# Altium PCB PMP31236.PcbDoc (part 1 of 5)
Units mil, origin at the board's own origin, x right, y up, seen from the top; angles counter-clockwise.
Board outline 6425 x 5322.16 mil, 6 copper layers (Top Layer, Power / GND 1, Signal Layer 1, Signal Layer 2, Power / GND 2, Bottom Layer), stack 78.712 mil thick; 732 components, 346 nets, 1735 pads, 719 vias.
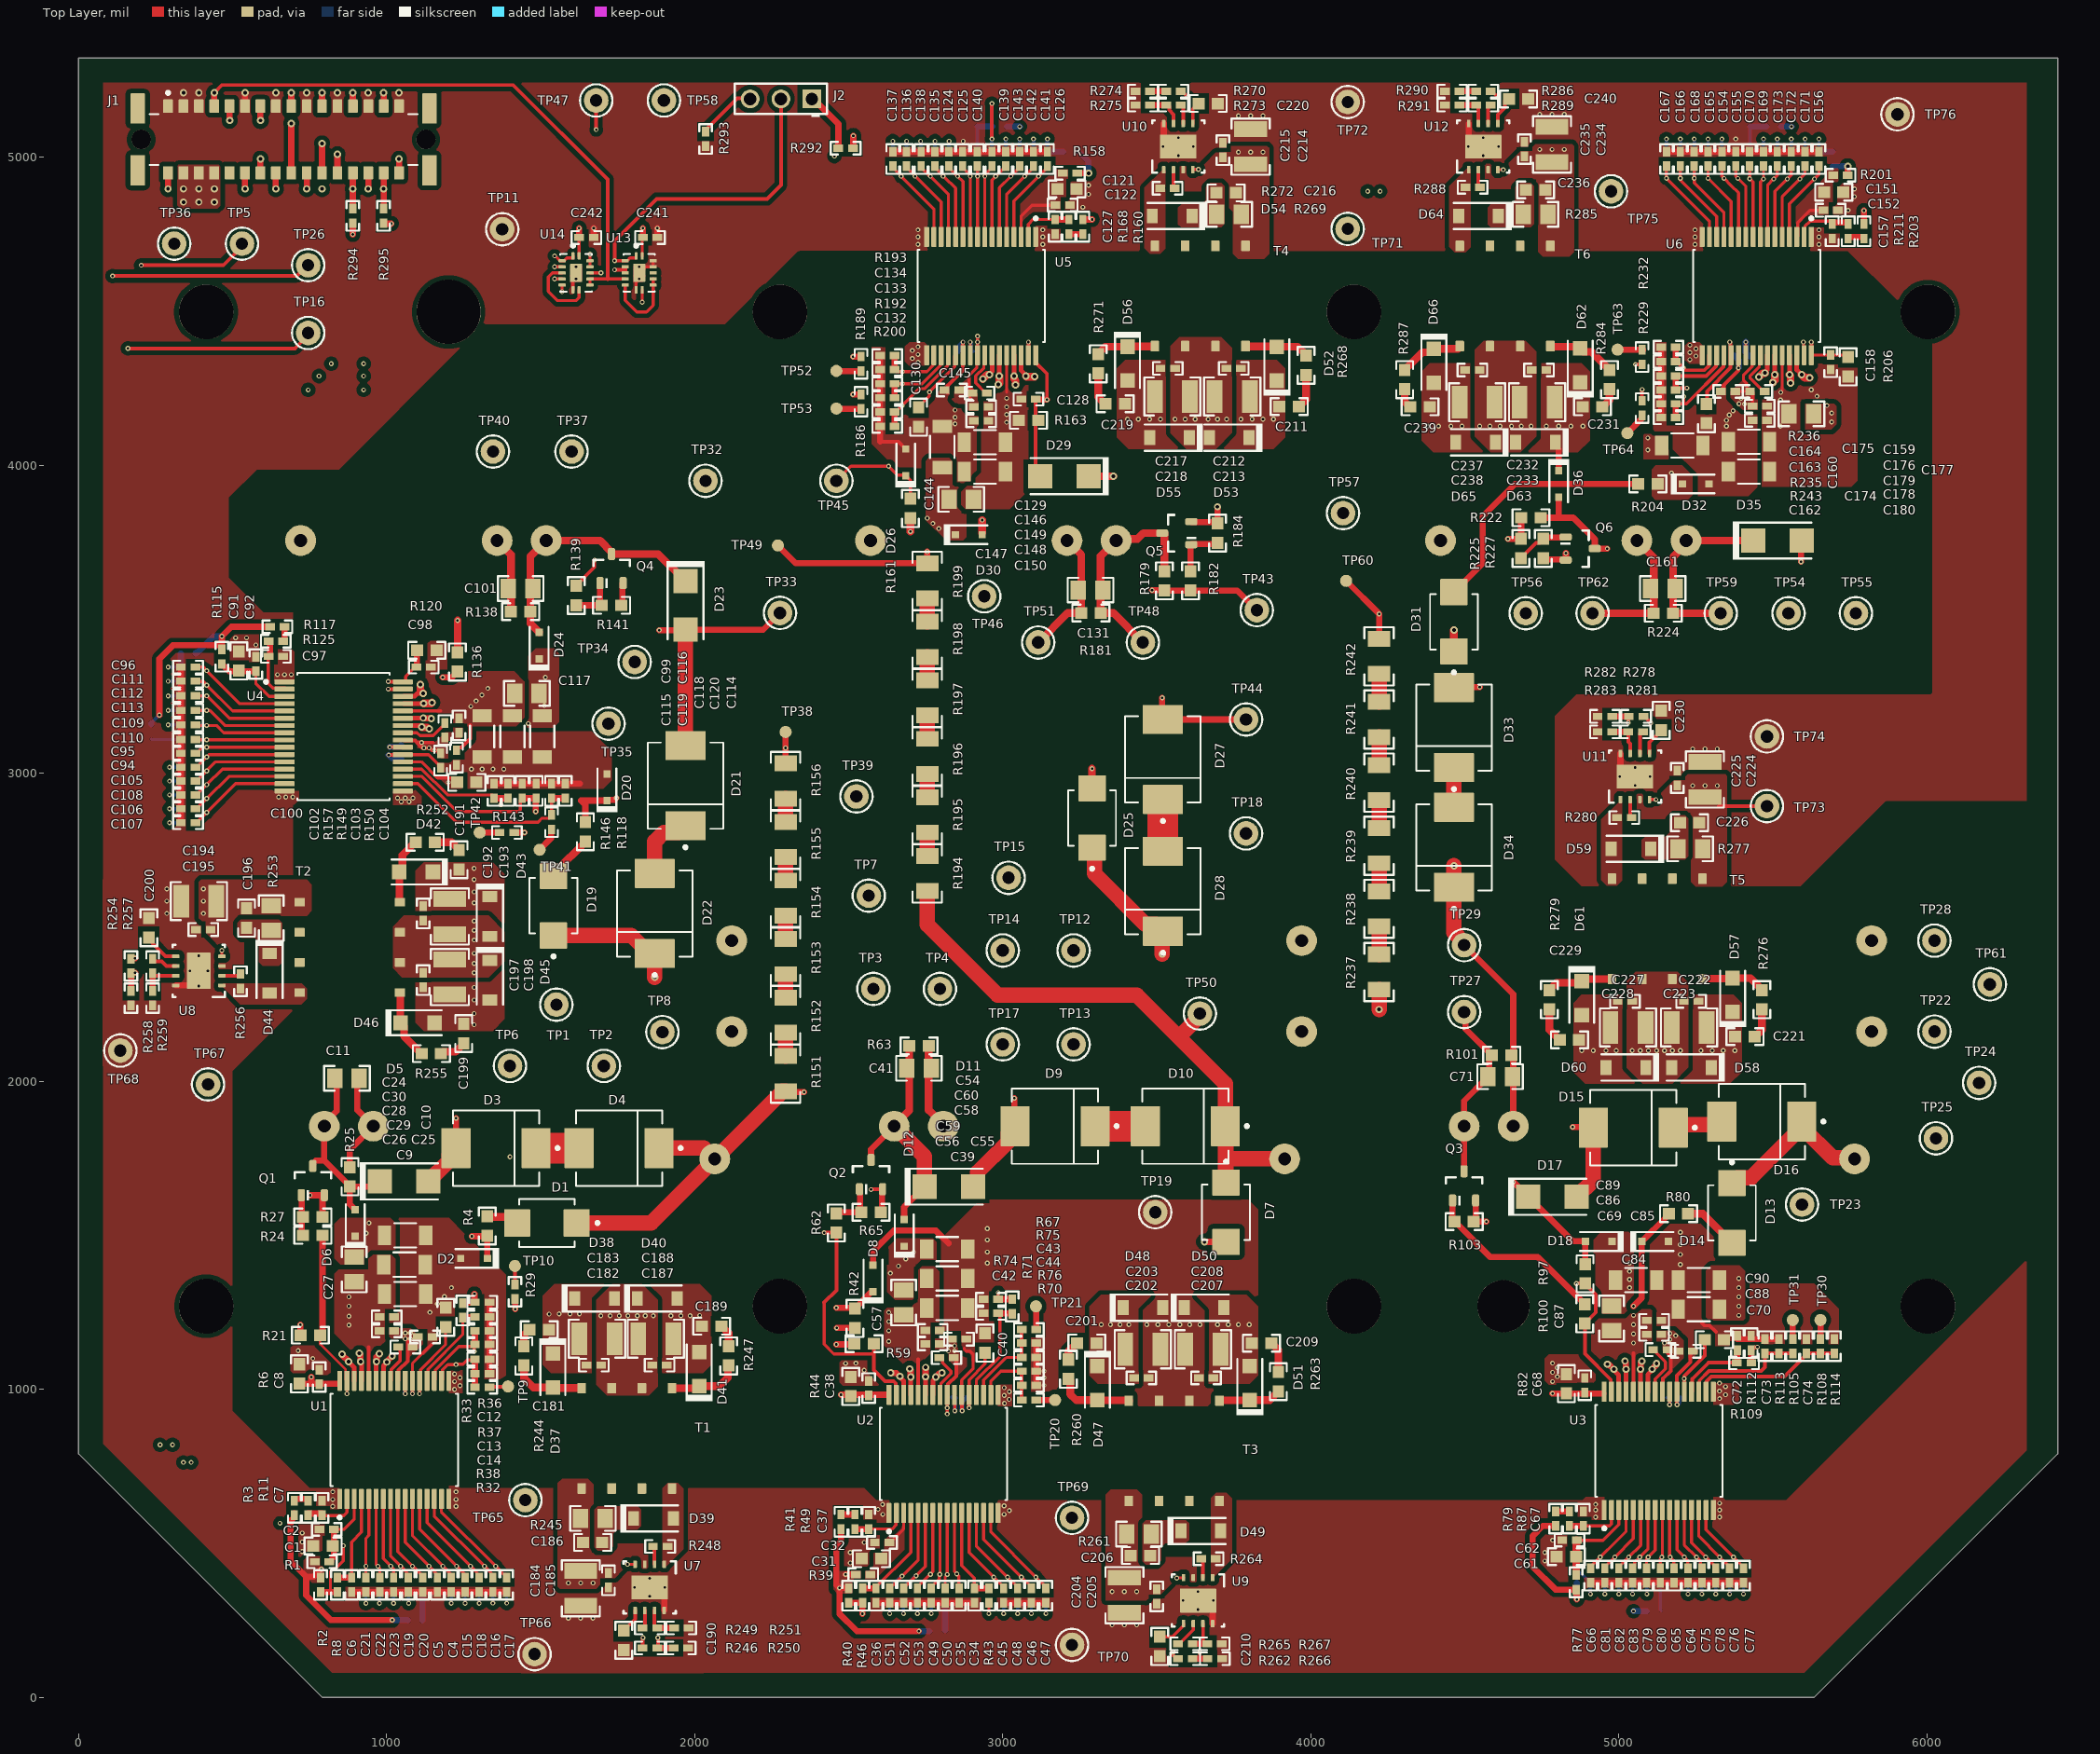
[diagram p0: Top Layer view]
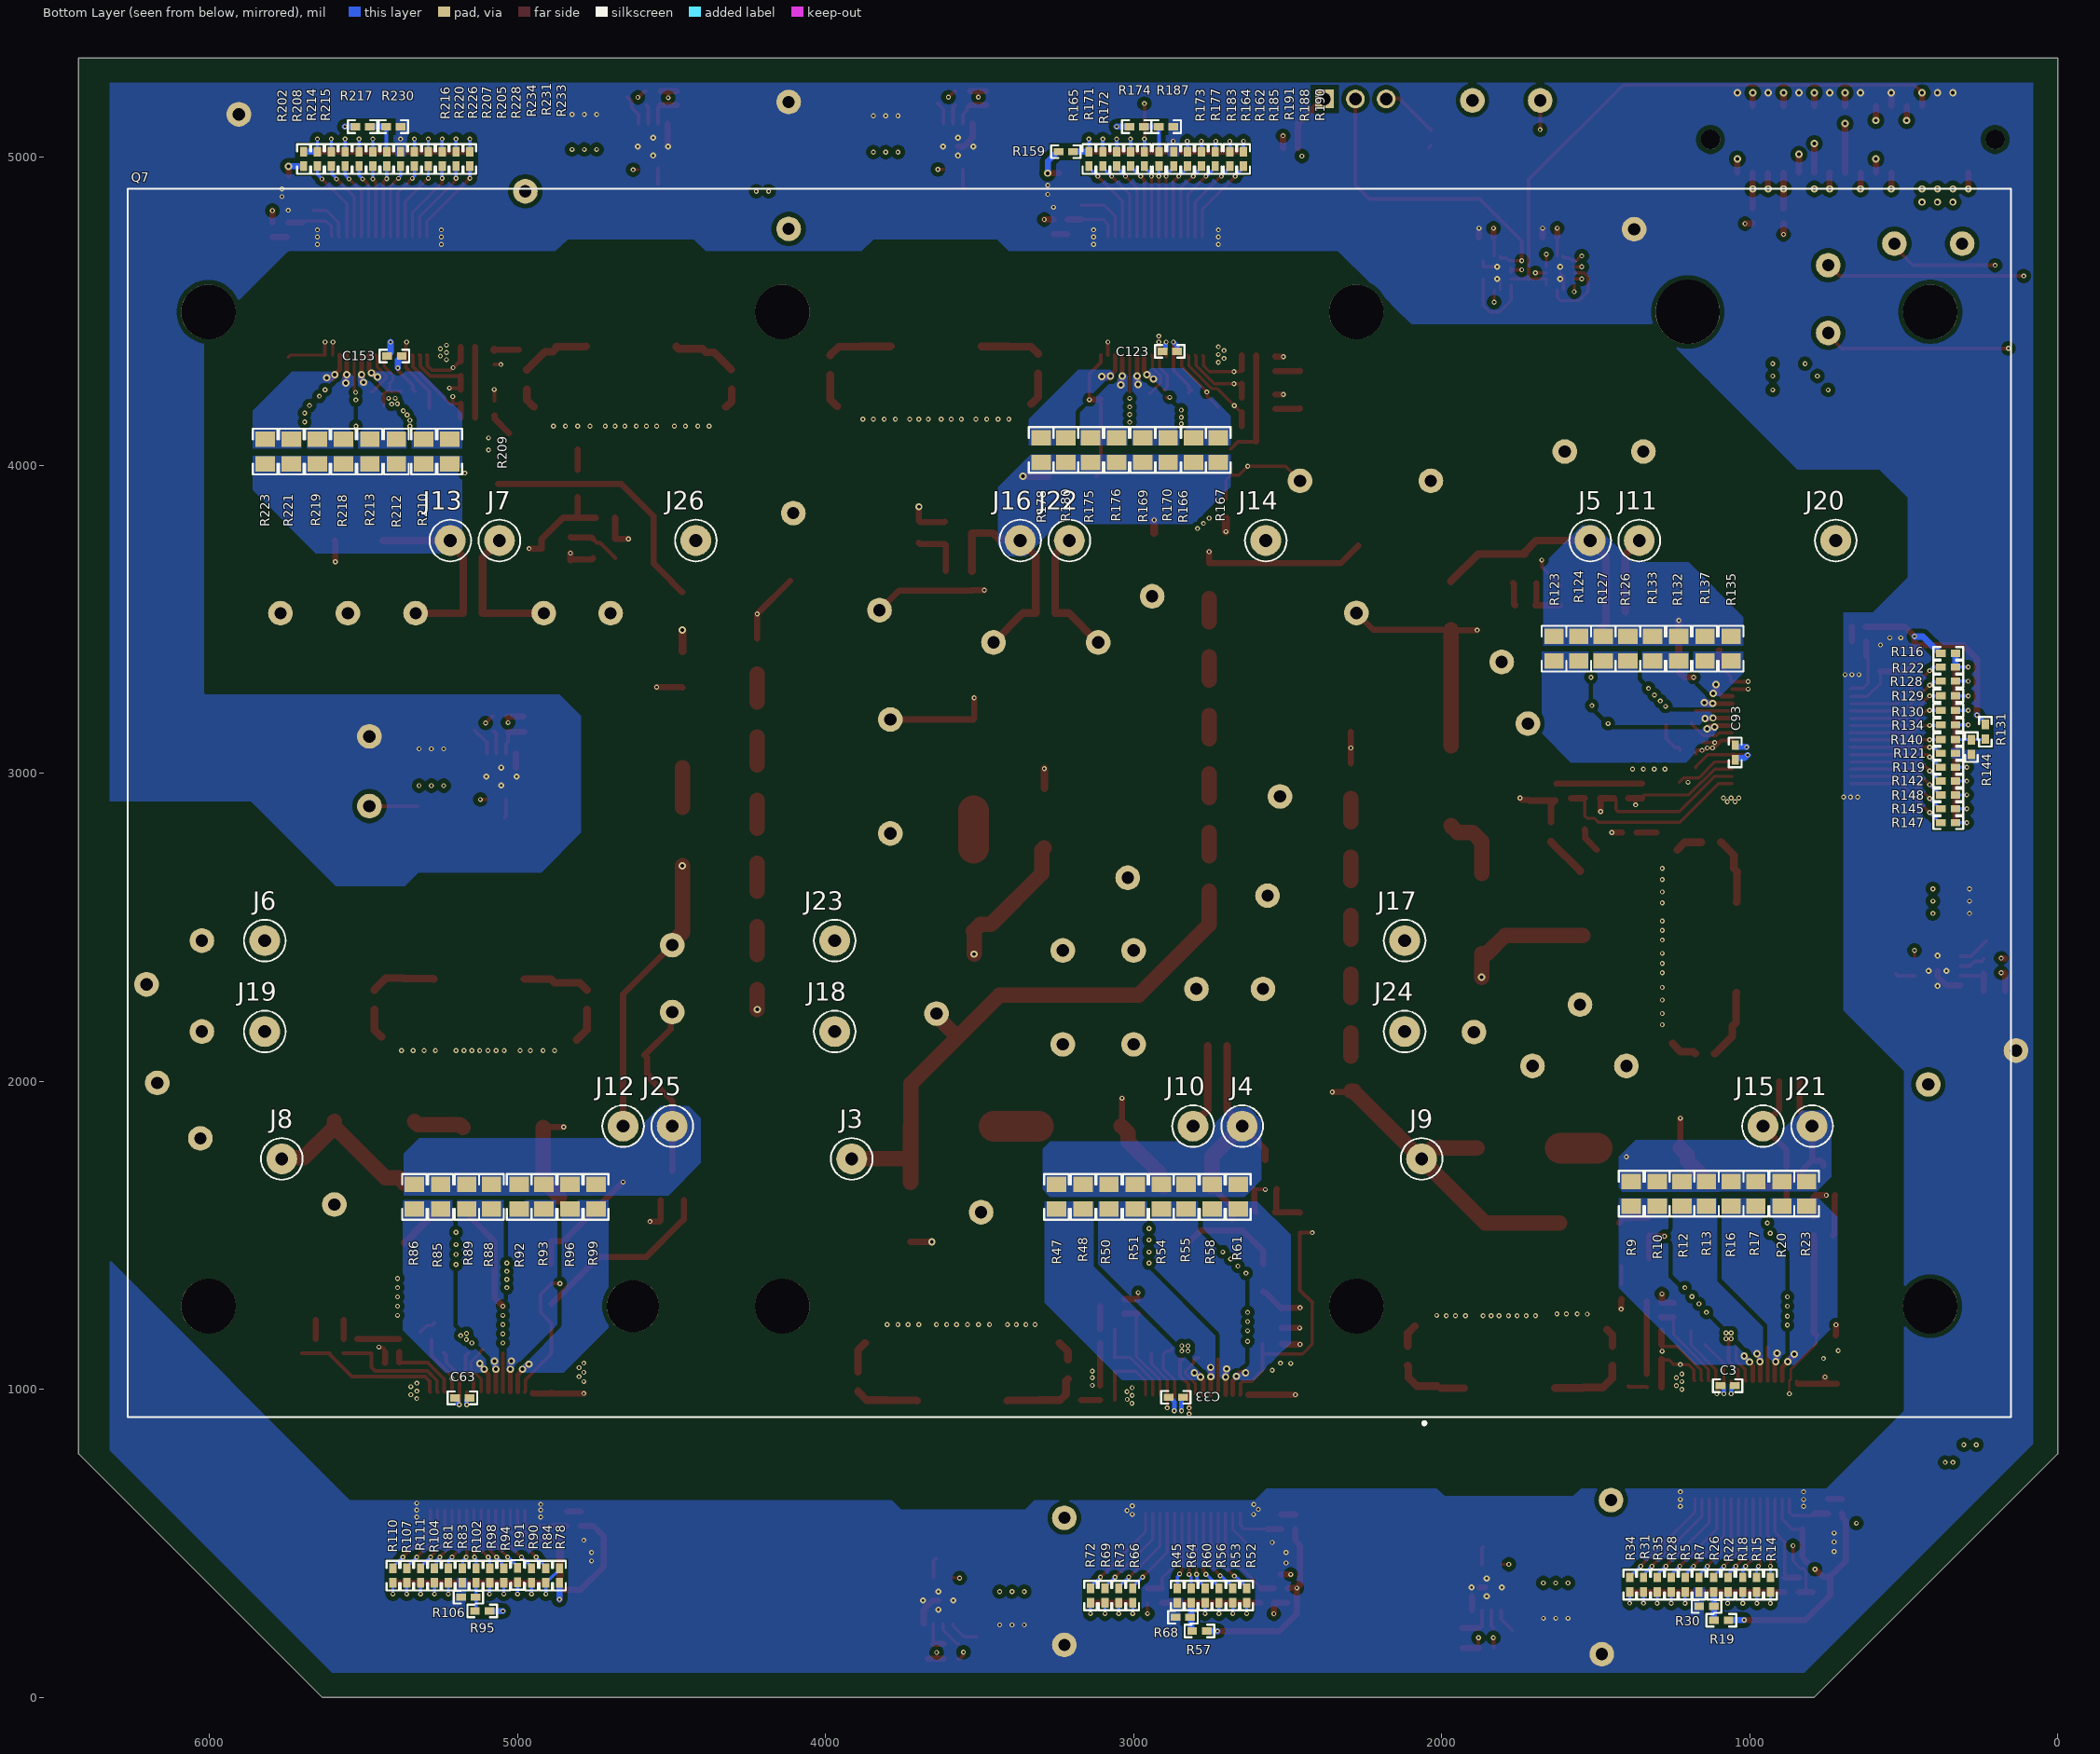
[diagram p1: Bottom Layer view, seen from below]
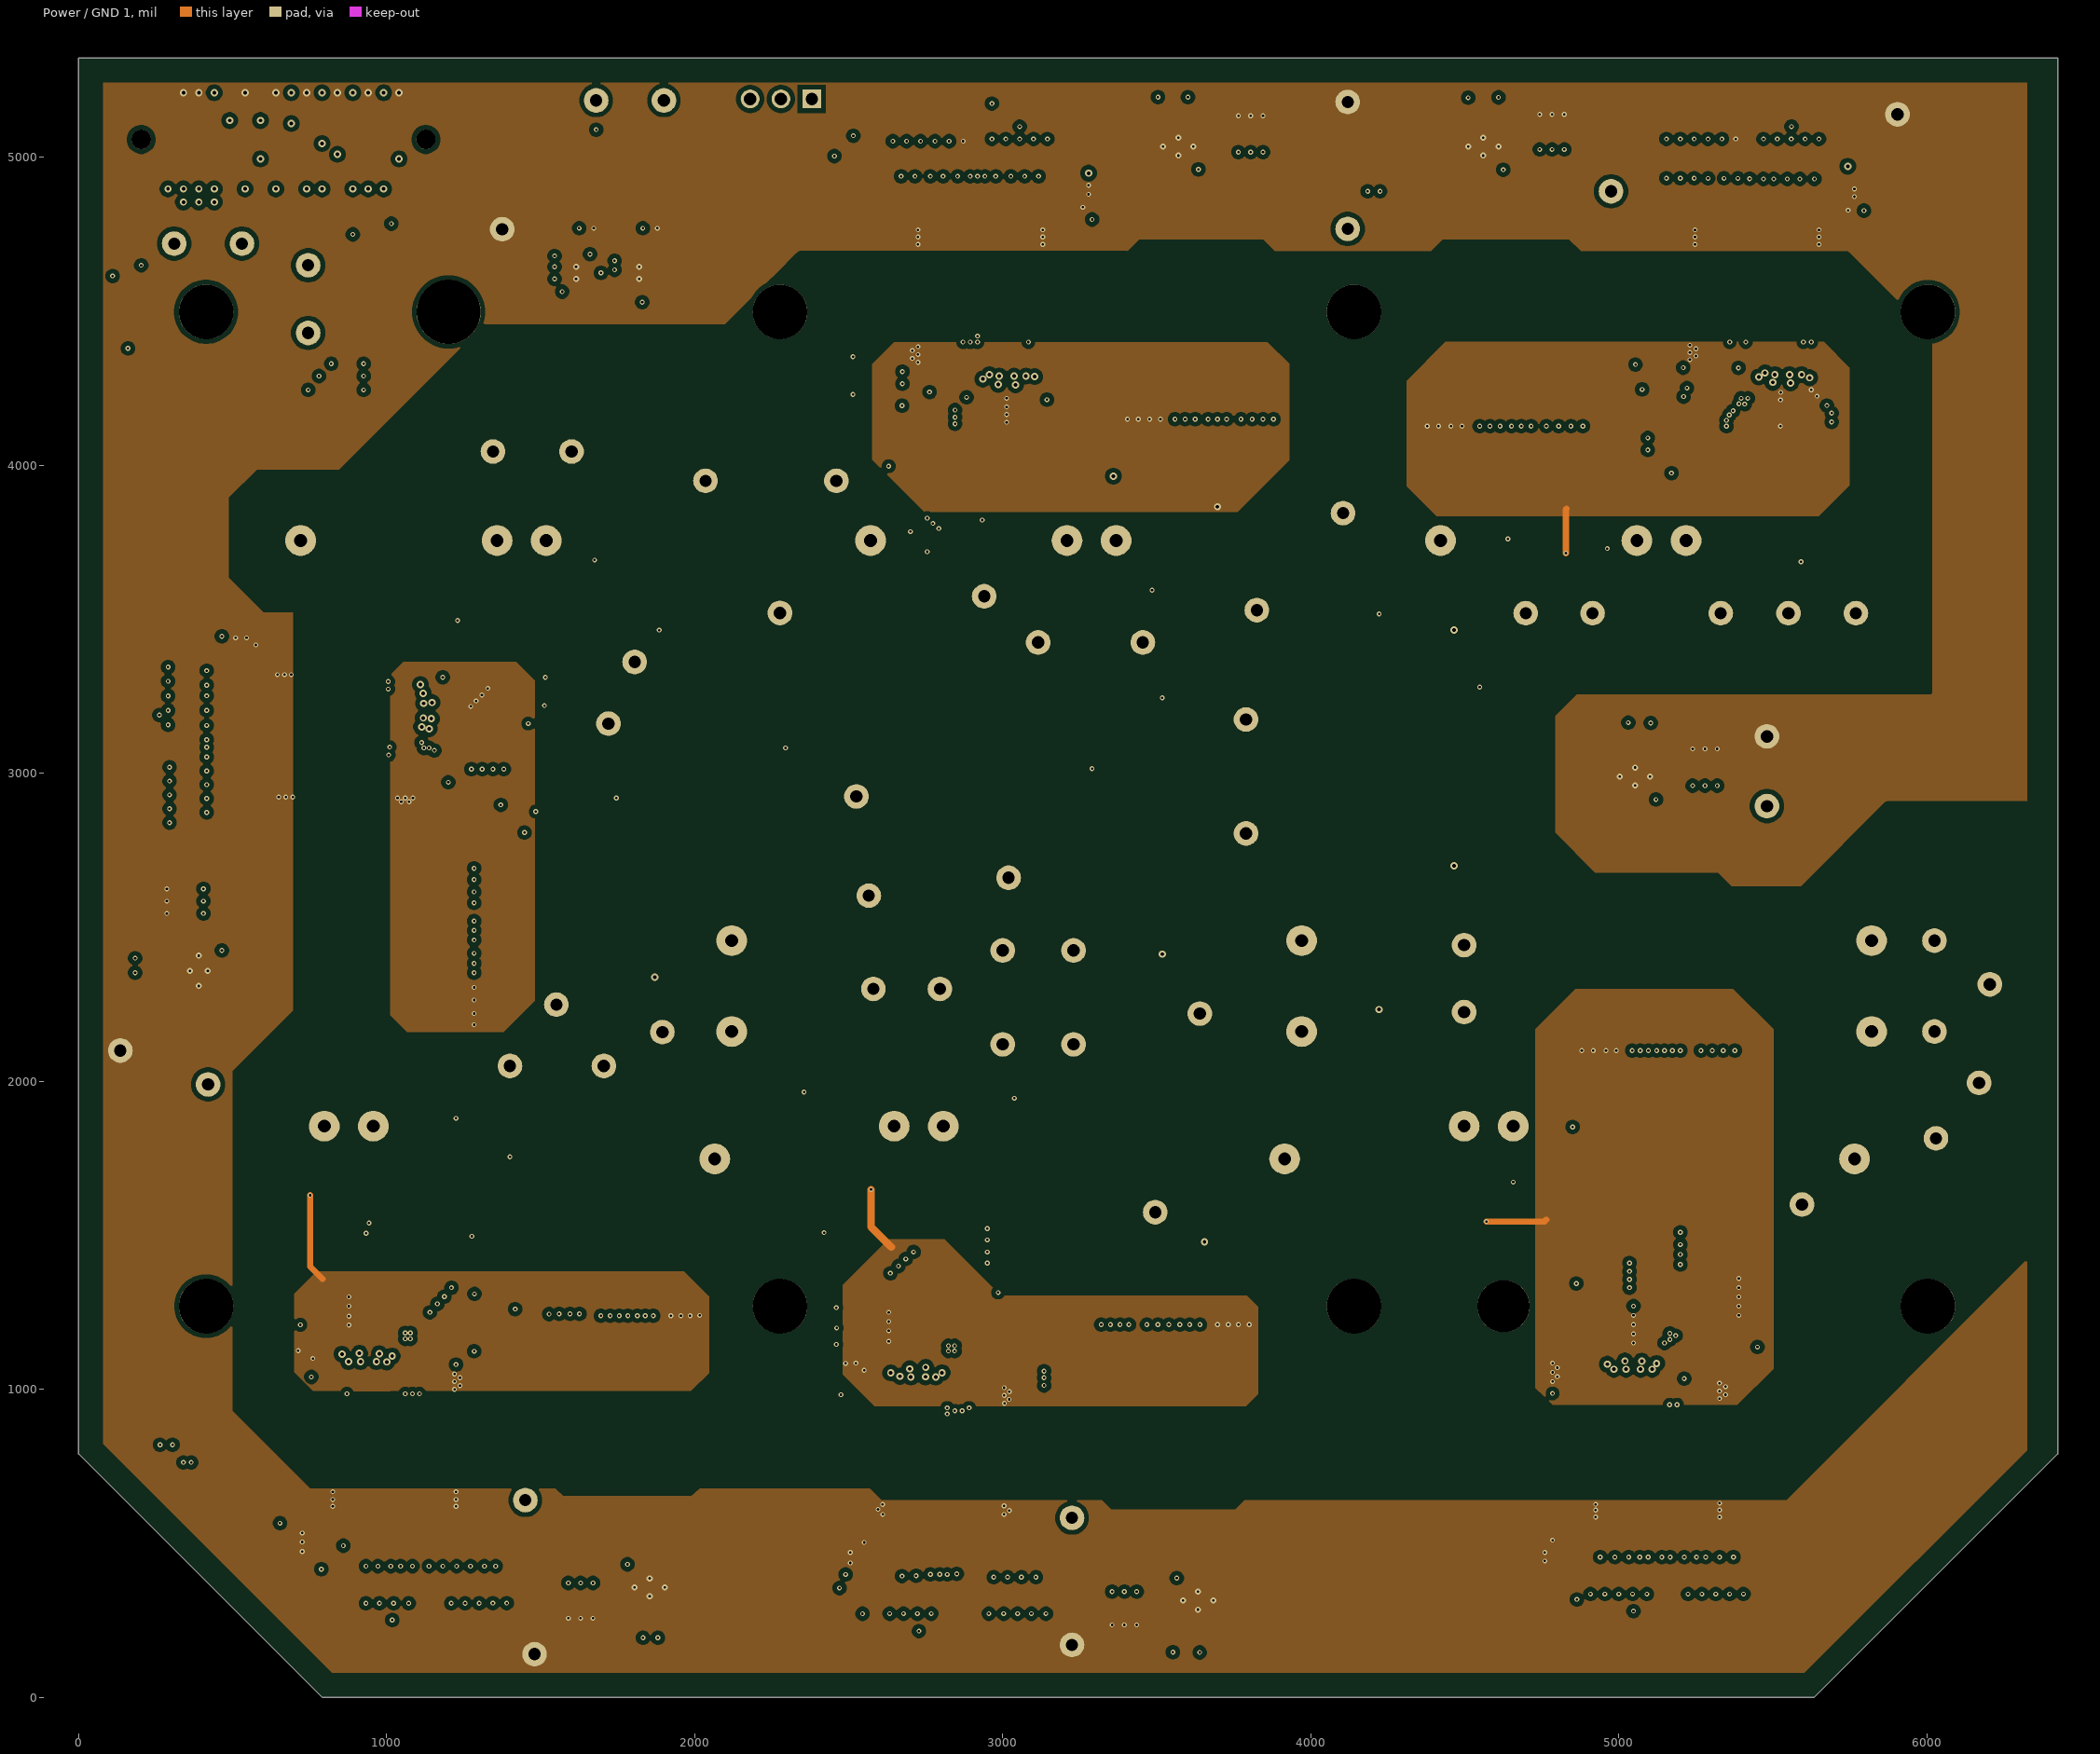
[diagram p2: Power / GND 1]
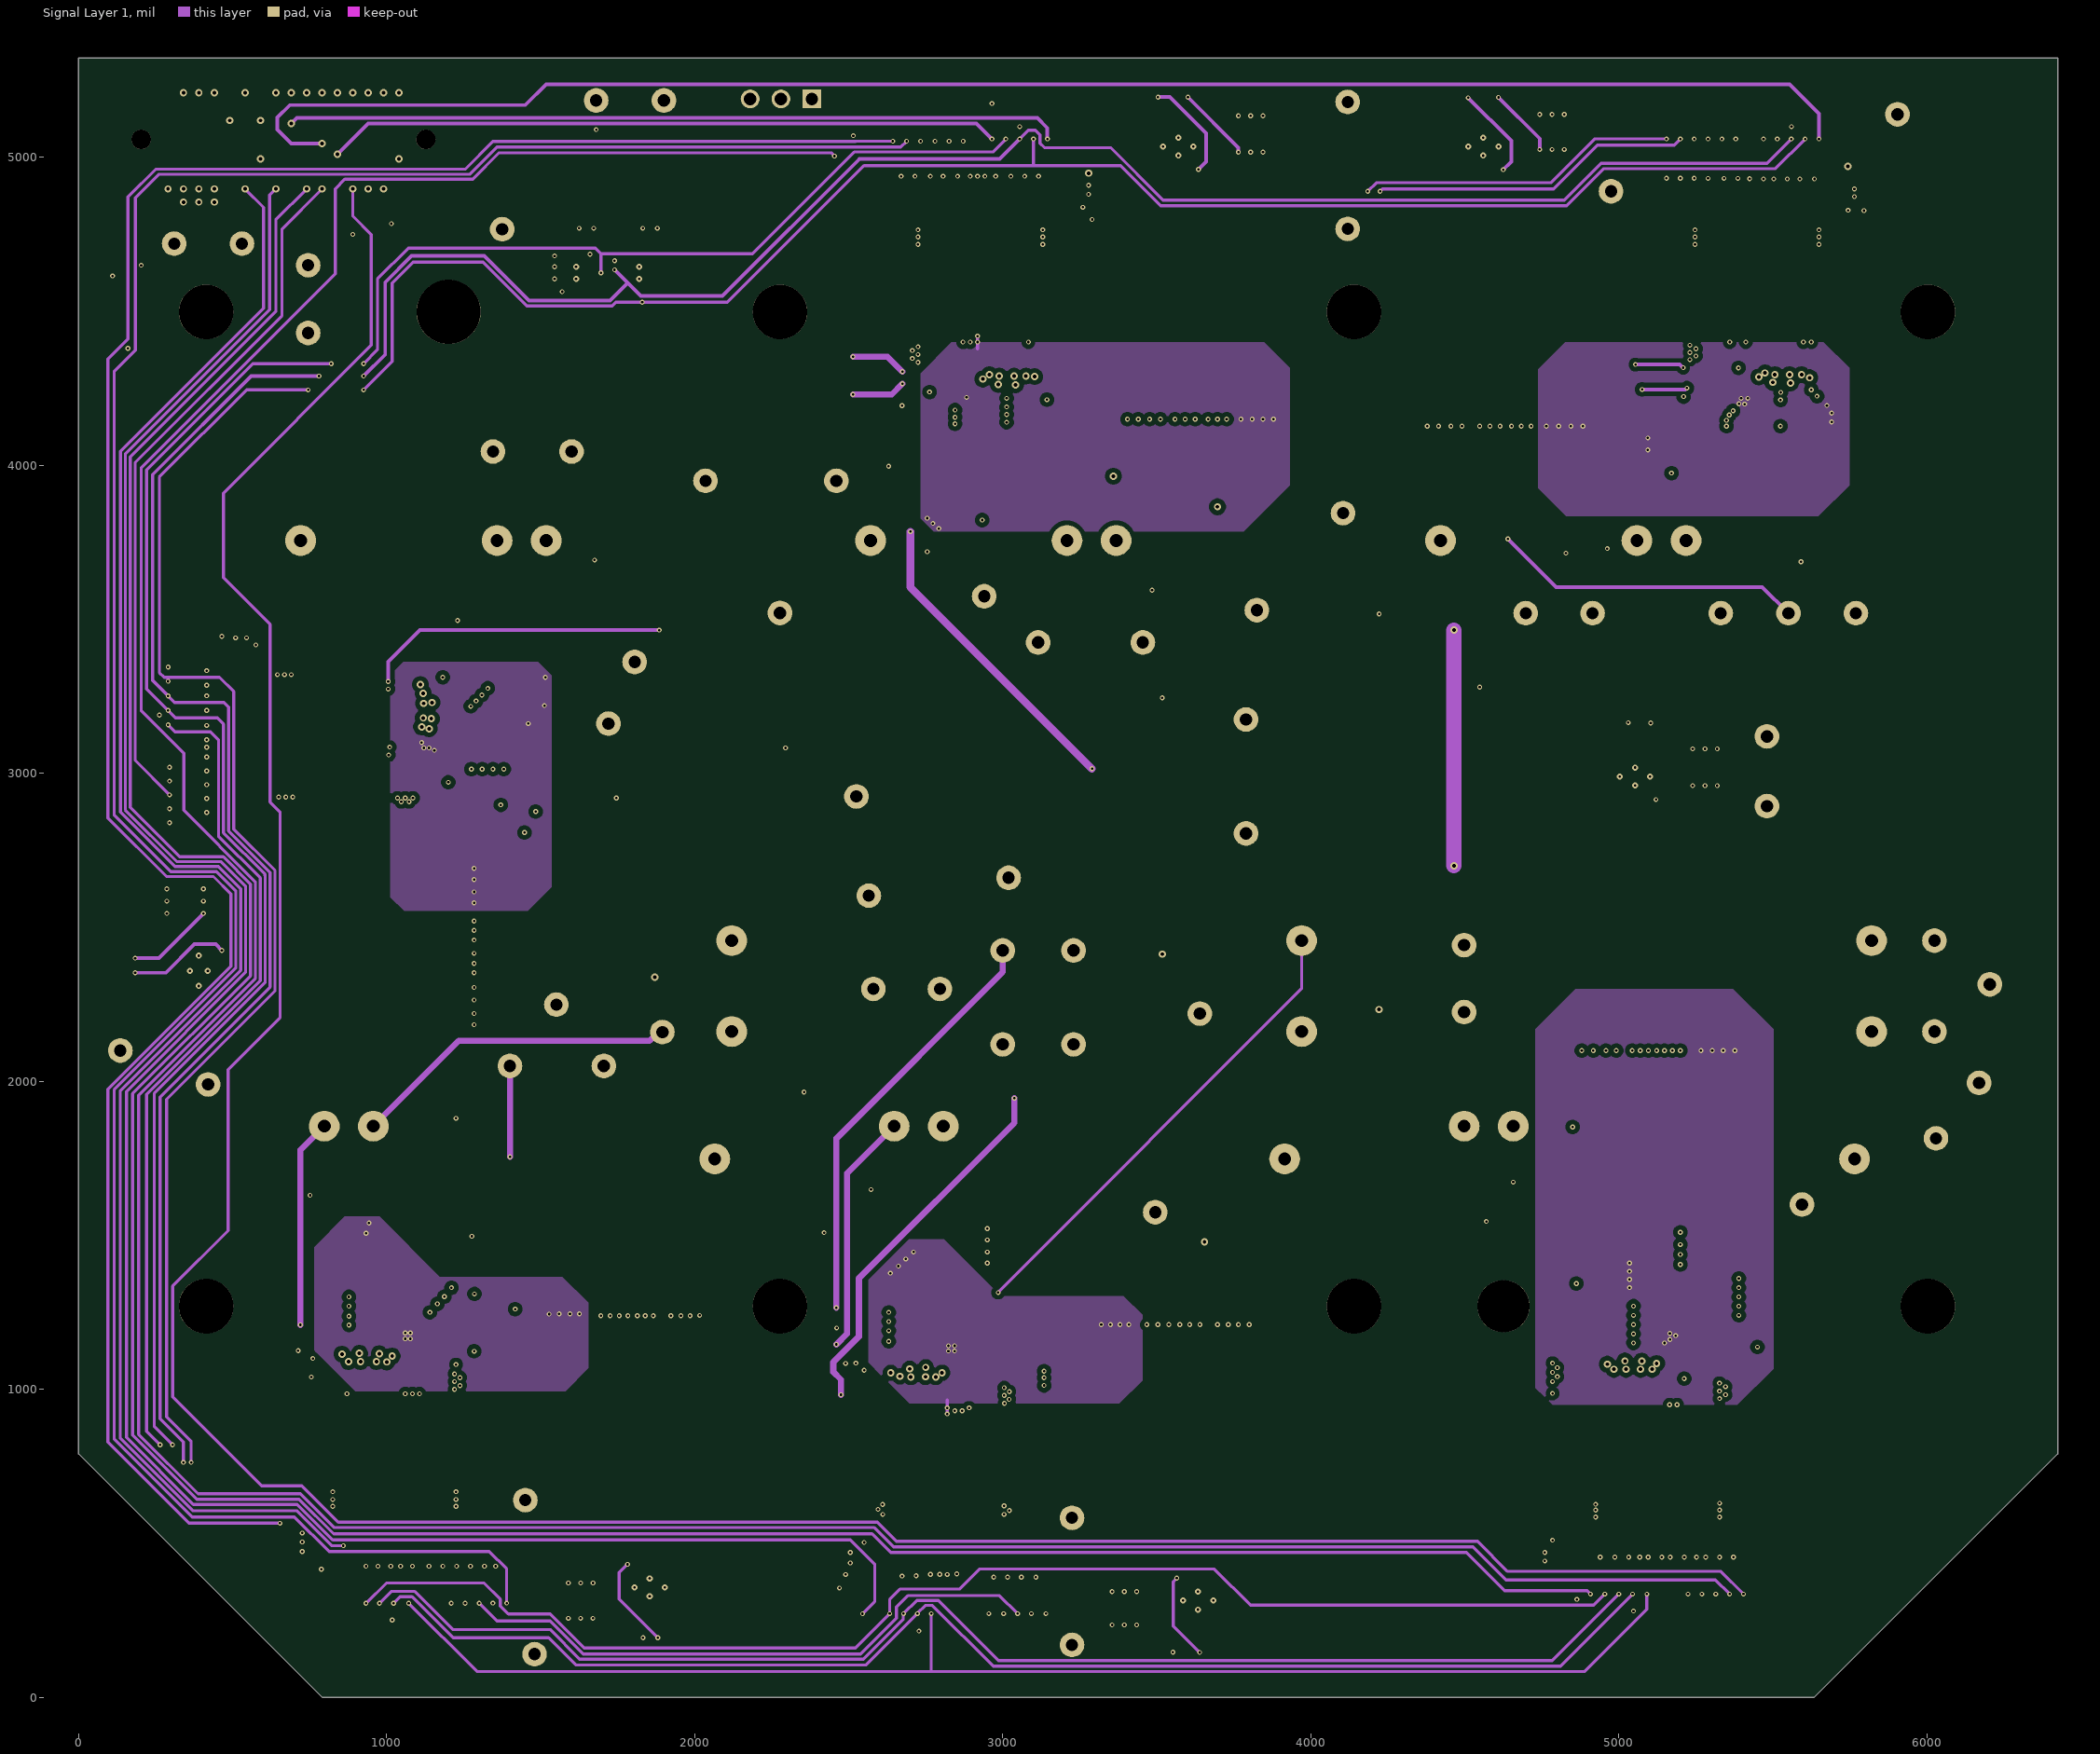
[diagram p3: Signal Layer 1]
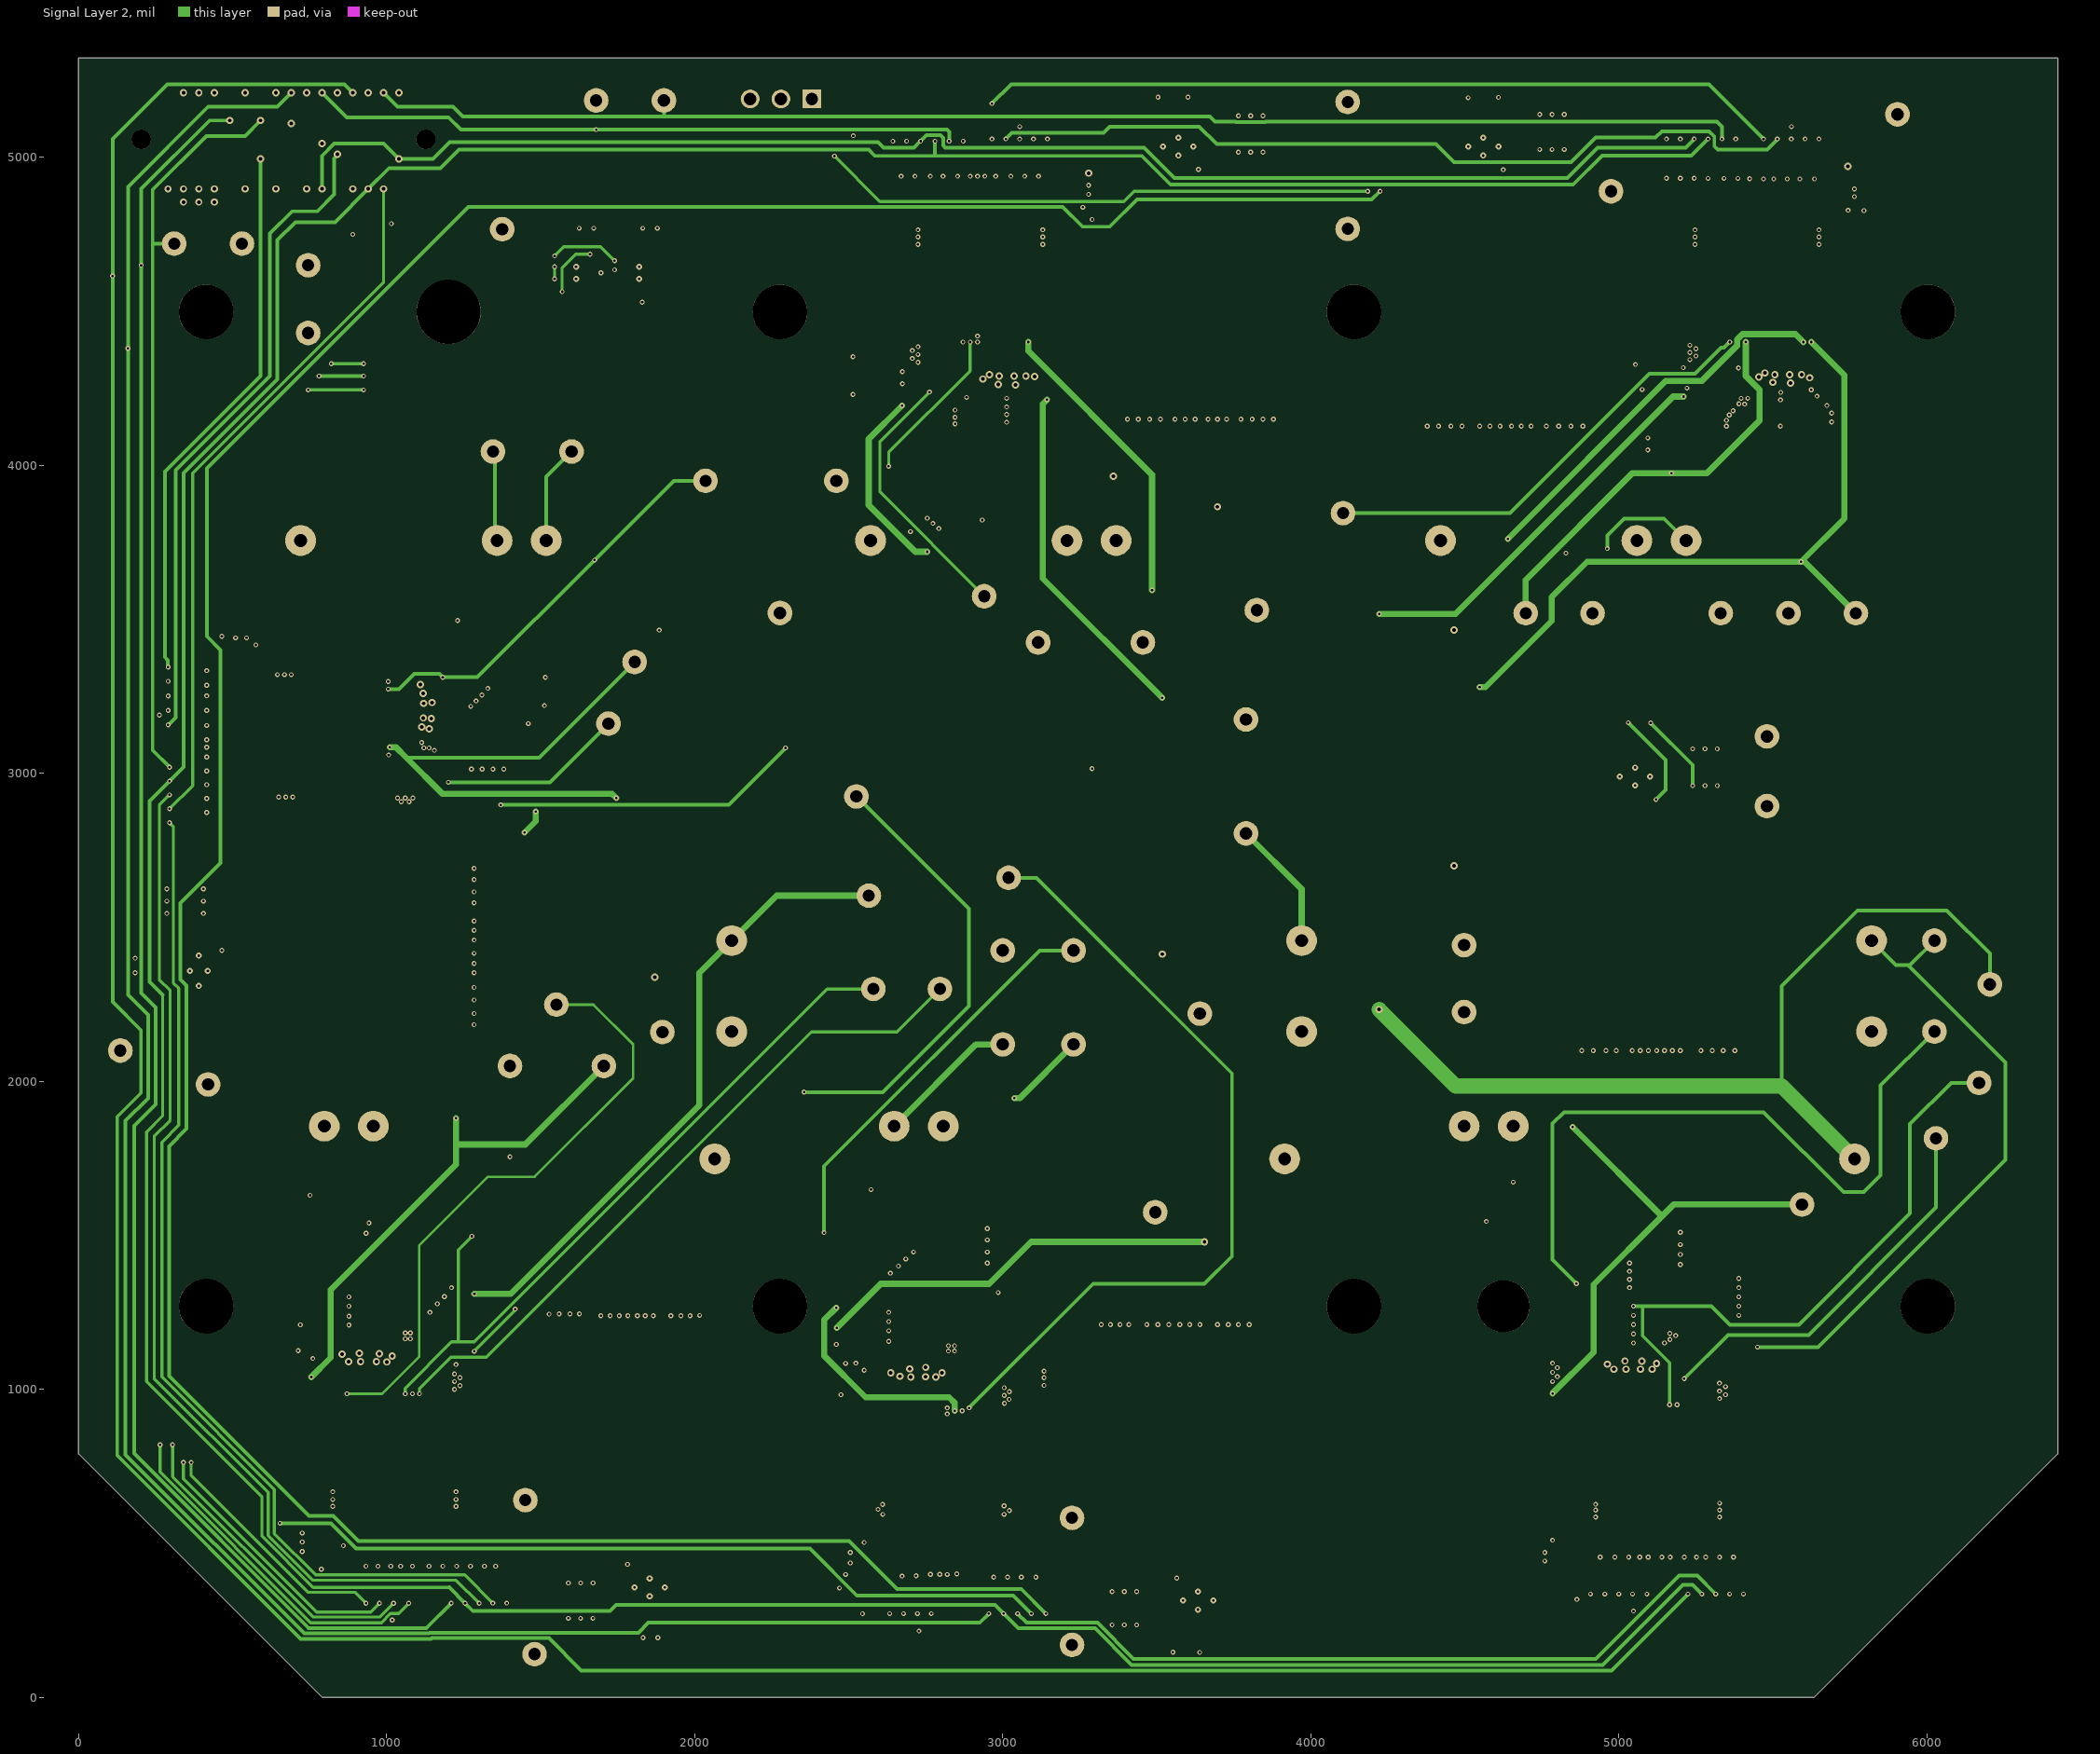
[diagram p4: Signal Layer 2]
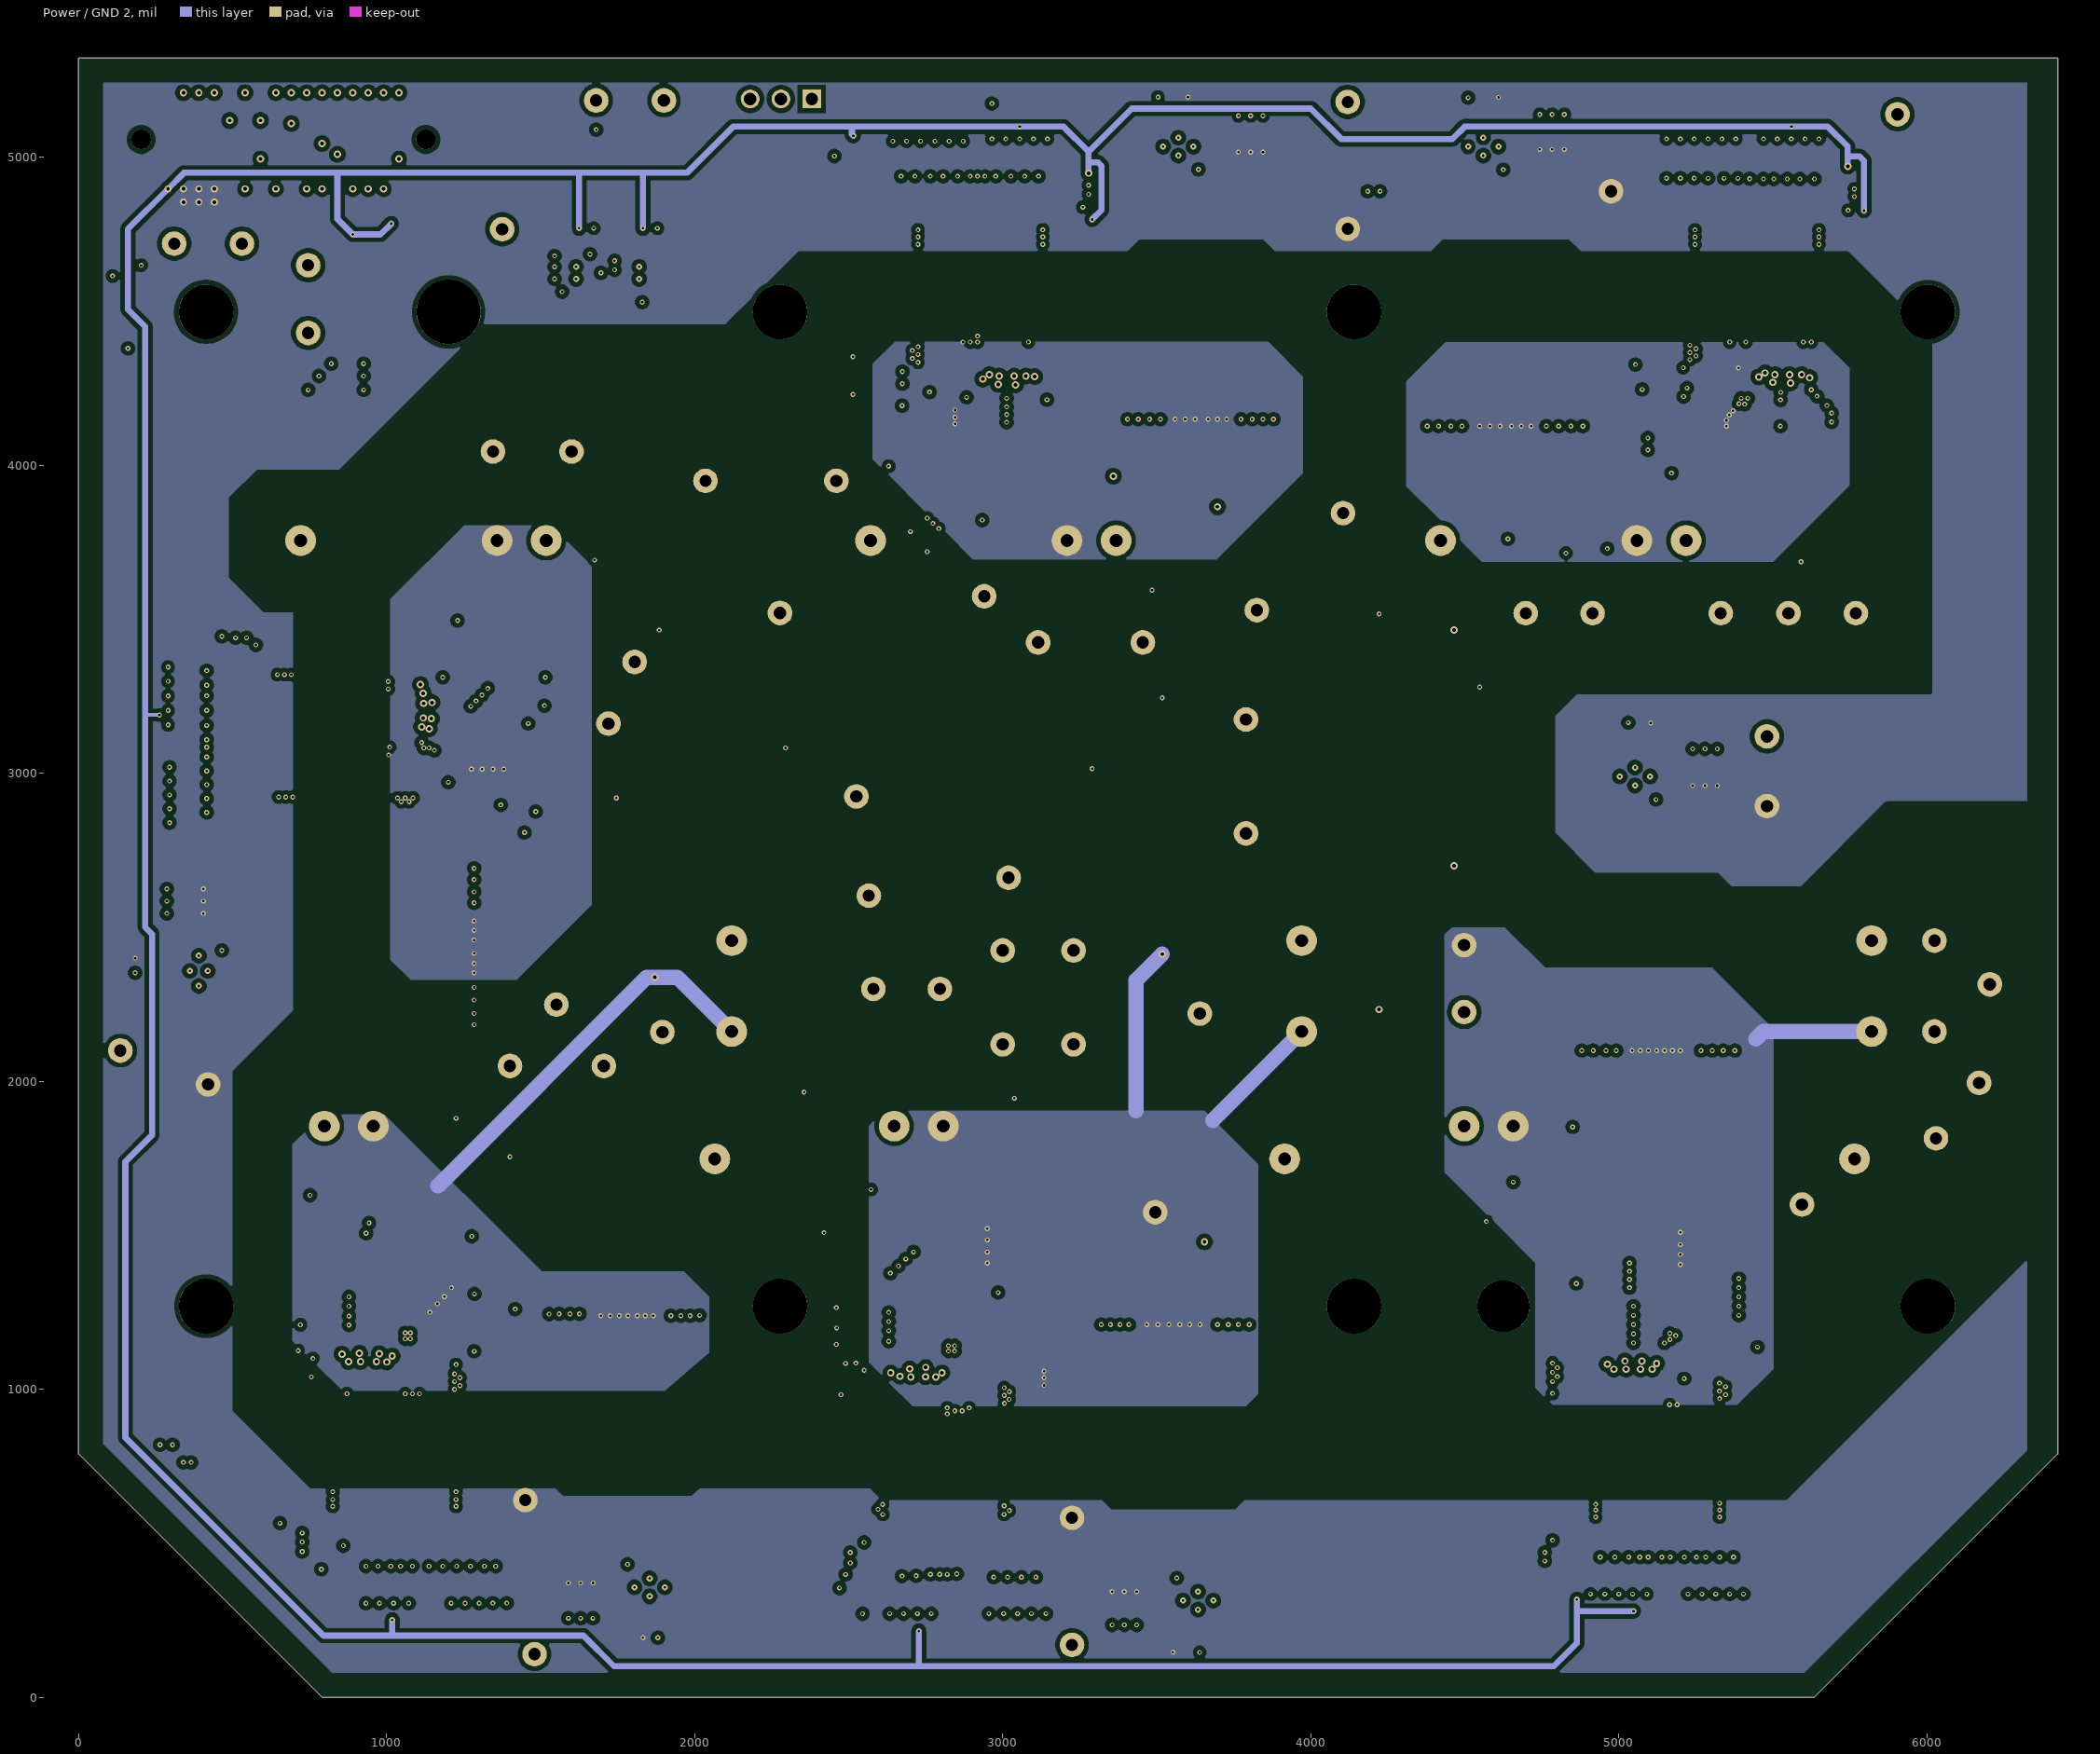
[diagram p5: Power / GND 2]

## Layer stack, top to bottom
Top Solder: solder mask 0.4, Solder Resist, Dk 3.5
Top Layer: signal copper 1.4
Dielectric 1: prepreg 2.8, PP-006, Dk 4.1
Power / GND 1: signal copper 1.378
Dielectric 3: prepreg 2.8, PP-006, Dk 4.1
Signal Layer 1: signal copper 1.378
Dielectric1: core 59.2, FR-4, Dk 4.8
Signal Layer 2: signal copper 1.378
Dielectric 4: prepreg 2.8, PP-006, Dk 4.1
Power / GND 2: signal copper 1.378
Dielectric 2: prepreg 2.8, PP-006, Dk 4.1
Bottom Layer: signal copper 1.4
Bottom Solder: solder mask 0.4, Solder Resist, Dk 3.5

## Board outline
5635,0 6425,790 6425,5322.16 0,5322.16 0,790 790,0

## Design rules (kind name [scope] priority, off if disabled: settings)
AcuteAngle [All] p1: minimum=4.50000000000000E+0001 checktracksonly=FALSE
AssemblyTestPointUsage [All] p1: valid=2
BoardOutlineClearance [All] p1: gap=78.74 ignorepadtopadclearanceinfootprint=FALSE
Clearance Clearance_Keepouts [((IsTrack Or IsArc) And Not InPoly) And IsFree and IsKeepOut vs ((IsTrack Or IsArc) And Not InPoly) And IsFree and IsKeepOut] p1: gap=0 ignorepadtopadclearanceinfootprint=FALSE
Clearance Clearance_BoardEdge_MountingHoles [OnCopper and InComponentClass('Mounting Holes') vs IsKeepOut] p2: gap=40 ignorepadtopadclearanceinfootprint=FALSE except(0: Arc-Hole Track-Hole SMDPad-Hole THPad-Hole Via-Hole Fill-Hole Poly-Hole Region-Hole Text-Hole)
Clearance Clearance_BoardEdge_Poly [OnCopper and InPoly vs IsKeepOut] p3: gap=25 ignorepadtopadclearanceinfootprint=FALSE except(0: Arc-Hole Track-Hole SMDPad-Hole THPad-Hole Via-Hole Fill-Hole Poly-Hole Region-Hole Text-Hole)
Clearance Clearance_BoardEdge [OnCopper and Not InComponentClass('Logo') and not InComponentClass('FiducialMark') and not InRegion(1000,500,4000,800) and Not IsKeepout vs IsKeepOut] p4: gap=75 ignorepadtopadclearanceinfootprint=FALSE except(0: Arc-Hole Track-Hole SMDPad-Hole THPad-Hole Via-Hole Fill-Hole Poly-Hole Region-Hole Text-Hole)
Clearance Clearance_Poly [InPolygon] p5: gap=15 ignorepadtopadclearanceinfootprint=FALSE except(0: Arc-Hole Track-Hole SMDPad-Hole THPad-Hole Via-Hole Fill-Hole Poly-Hole Region-Hole Text-Hole)
Clearance [All] p6: gap=5.91 ignorepadtopadclearanceinfootprint=FALSE
ComponentClearance ComponentClearance_MountingHoles_FiducialMarks [InComponentClass('Mounting Holes') vs InComponentClass('FiducialMark')] p1: gap=50 collisioncheckmode=3 verticalgap=10 showdistances=FALSE
ComponentClearance ComponentClearance_Shunt [InComponentClass('Header') vs InComponentClass('Shunt')] p2: gap=0 collisioncheckmode=3 verticalgap=0 showdistances=FALSE
ComponentClearance ComponentClearance_Logo [InComponentClass('Logo')] p3: gap=50 collisioncheckmode=3 verticalgap=10 showdistances=FALSE
ComponentClearance ComponentClearance_ScrewToNut [(HasFootprint('NY PMS 440 0025 PH')) vs (HasFootprint('Keystone_1902C'))] p4: gap=5 collisioncheckmode=3 verticalgap=10 showdistances=FALSE
ComponentClearance ComponentClearance_MountingHoles [InComponentClass('Mounting Holes')] p5: gap=250 collisioncheckmode=3 verticalgap=100000 showdistances=FALSE
ComponentClearance ComponentClearance_SmallPassives [HasFootprint('0201*') or HasFootprint('0402*') or HasFootprint('0508') or HasFootprint('0603*') or HasFootprint('0612') or HasFootprint('0805*') or HasFootprint('0815*') or HasFootprint('0830*') or HasFootprint('1206*') or HasFootprint('1210*') or HasFootprint('1808*') or HasFootprint('1812*') or HasFootprint('1825*') or HasFootprint('2010*') or HasFootprint('2220*') or HasFootprint('2225*') or HasFootprint('2512*') or HasFootprint('2728*') or HasFootprint('3518*') vs HasFootprint('0201*') or HasFootprint('0402*') or HasFootprint('0508') or HasFootprint('0603*') or HasFootprint('0612') or HasFootprint('0805*') or HasFootprint('0815*') or HasFootprint('0830*') or HasFootprint('1206*') or HasFootprint('1210*') or HasFootprint('1808*') or HasFootprint('1812*') or HasFootprint('1825*') or HasFootprint('2010*') or HasFootprint('2220*') or HasFootprint('2225*') or HasFootprint('2512*') or HasFootprint('2728*') or HasFootprint('3518*')] p6: gap=20 collisioncheckmode=3 verticalgap=10 showdistances=FALSE
ComponentClearance ComponentClearance_THtoSMT [IsThruComponent vs IsSMTComponent] p7: gap=100 collisioncheckmode=3 verticalgap=30 showdistances=FALSE
ComponentClearance ComponentClearance_THtoTH [IsThruComponent vs IsThruComponent] p8: gap=118.11 collisioncheckmode=3 verticalgap=30 showdistances=FALSE
ComponentClearance [All] p9: gap=40 collisioncheckmode=3 verticalgap=10 showdistances=FALSE
DiffPairsRouting [All] p1: maxlimit=100 minlimit=10 mostfreqgap=10 toplayer_minwidth=15 toplayer_maxwidth=15 toplayer_prefwidth=15 midlayer1_minwidth=15 midlayer1_maxwidth=15 midlayer1_prefwidth=15 midlayer2_minwidth=15 midlayer2_maxwidth=15 midlayer2_prefwidth=15 midlayer3_minwidth=15 midlayer3_maxwidth=15 midlayer3_prefwidth=15 midlayer4_minwidth=15 midlayer4_maxwidth=15 midlayer4_prefwidth=15 bottomlayer_minwidth=15 bottomlayer_maxwidth=15 bottomlayer_prefwidth=15 maxuncoupledlength=1000
FabricationTestPointUsage TestPointUsage [All] p1: valid=2 allowmultiple=FALSE
FabricationTestpoint Testpoint [All] p1: side=3 testpointundercomponent=TRUE minsize=40 maxsize=100 preferedsize=60 minholesize=0 maxholesize=40 preferedholesize=32 testpointgrid=1 allowsidetop=TRUE allowsidebottom=TRUE usegrid=TRUE gridtolerance=0.01
FanoutControl Fanout_LCC [IsLCC] p1: bgadir=Out bgaviamode=Centered fanoutstyle=Auto fanoutdirection=Alternating viagrid=1 // Fanout_LCC (Default Rule)
FanoutControl Fanout_BGA [IsBGA] p2: bgadir=Out bgaviamode=Centered fanoutstyle=Auto fanoutdirection=Alternating viagrid=1 // Fanout_BGA (Default Rule)
FanoutControl Fanout_Default [All] p4: bgadir=Out bgaviamode=Centered fanoutstyle=Auto fanoutdirection=Alternating viagrid=1 // Fanout_Default (Default Rule)
FanoutControl Fanout_Small [(CompPinCount < 5)] p5: bgadir=Out bgaviamode=Centered fanoutstyle=Auto fanoutdirection=OutThenIn viagrid=1 // Fanout_Small (Default Rule)
HoleSize [All] p1: absolutevalues=TRUE maxlimit=251 minlimit=7.87 maxpercent=80.000 minpercent=20.000
MinimumAnnularRing MinimumAnnularRing_ThermalPadVias [IsVia and InAnyComponent] p1: minimumring=5.91
MinimumAnnularRing [All] p2: minimumring=3.94
MinimumSolderMaskSliver MinimumSolderMaskSliver_Logo [InComponentClass('Logo') vs InComponentClass('Logo')] p1: minsoldermaskwidth=0.7
MinimumSolderMaskSliver [All] p2: minsoldermaskwidth=3.94
PlaneConnect [All] p1: planeconnectstyle=Relief reliefexpansion=10 reliefentries=4 reliefconductorwidth=10 reliefairgap=10
PolygonConnect [All] p1: connectstyle=Direct reliefconductorwidth=10 reliefentries=4 polygonreliefangle="90 Angle" airgapwidth=10
RoutingVias ThermalPadVias [IsVia and InAnyComponent] p1: holewidth=7.87 width=19.68 viastyle="Through Hole" minholewidth=7.87 minwidth=15.75 maxholewidth=12.99 maxwidth=23.62
RoutingVias [All] p2: holewidth=11.81 width=23.62 viastyle="Through Hole" minholewidth=7.87 minwidth=15.75 maxholewidth=40 maxwidth=65
SilkToBoardRegionClearance [Not ((IsComment or IsDesignator) And (Hide <> 'False')) and not InRegion(1000,500,4000,800)] p1:
SilkToSilkClearance SilkToSilkClearance_Pb-FreeLogo [(HasFootprint('Pb-Free_Overlay_Medium') OR HasFootprint('Pb-Free_Overlay_Small')) vs (HasFootprint('Pb-Free_Overlay_Medium') OR HasFootprint('Pb-Free_Overlay_Small'))] p1: silktosilkclearance=0
SilkToSilkClearance [All] p2: silktosilkclearance=4
SilkToSolderMaskClearance SilkToComonentPadClearance [IsPad and InAnycomponent] p1: minsilkscreentomaskgap=5 clearancetoexposedcopper=TRUE
SilkToSolderMaskClearance "Silk to Solder Mask Opening" [All] p2: minsilkscreentomaskgap=4 clearancetoexposedcopper=FALSE
SolderMaskExpansion [All] p1: expansion=1.97 istentingtop=FALSE
Width [All] p1: maxlimit=100 minlimit=6 preferedwidth=10 checkconnectedcopper=TRUE
15 further rules are at their usual default settings.

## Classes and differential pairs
component class PMP31236RevA_IGBT_Module: J3 J4 J5 J6 J7 J8 J9 J10 J11 J12 J13 J14 J15 J16 J17 J18 J19 J20 J21 J22 J23 J24 J25 J26 Q7
component class PMP31236RevA_Supply_W: C221 C222 C223 C224 C225 C226 C227 C228 C229 C230 C231 C232 C233 C234 C235 C236 C237 C238 C239 C240 D57 D58 D59 D60 D61 D62 D63 D64 D65 D66 R276 R277 R278 R279 R280 R281 R282 R283 R284 R285 R286 R287 R288 R289 R290 R291 T5 T6 TP73 TP74 TP75 TP76 U11 U12
component class PMP31236RevA_Supply_V: C201 C202 C203 C204 C205 C206 C207 C208 C209 C210 C211 C212 C213 C214 C215 C216 C217 C218 C219 C220 D47 D48 D49 D50 D51 D52 D53 D54 D55 D56 R260 R261 R262 R263 R264 R265 R266 R267 R268 R269 R270 R271 R272 R273 R274 R275 T3 T4 TP69 TP70 TP71 TP72 U9 U10
component class PMP31236RevA_Supply_U: C181 C182 C183 C184 C185 C186 C187 C188 C189 C190 C191 C192 C193 C194 C195 C196 C197 C198 C199 C200 D37 D38 D39 D40 D41 D42 D43 D44 D45 D46 R244 R245 R246 R247 R248 R249 R250 R251 R252 R253 R254 R255 R256 R257 R258 R259 T1 T2 TP65 TP66 TP67 TP68 U7 U8
component class PMP31236RevA_LS_W: C151 C152 C153 C154 C155 C156 C157 C158 C159 C160 C161 C162 C163 C164 C165 C166 C167 C168 C169 C170 C171 C172 C173 C174 C175 C176 C177 C178 C179 C180 D31 D32 D33 D34 D35 D36 Q6 R201 R202 R203 R204 R205 R206 R207 R208 R209 R210 R211 R212 R213 R214 R215 R216 R217 R218 R219 R220 R221 R222 R223 R224 R225 R226 R227 R228 R229 R230 R231 R232 R233 R234 R235 R236 R237 R238 R239 R240 R241 R242 R243 TP54 TP55 TP56 TP57 TP58 TP59 TP60 TP61 TP62 TP63 TP64 U6
component class PMP31236RevA_LS_V: C121 C122 C123 C124 C125 C126 C127 C128 C129 C130 C131 C132 C133 C134 C135 C136 C137 C138 C139 C140 C141 C142 C143 C144 C145 C146 C147 C148 C149 C150 D25 D26 D27 D28 D29 D30 Q5 R158 R159 R160 R161 R162 R163 R164 R165 R166 R167 R168 R169 R170 R171 R172 R173 R174 R175 R176 R177 R178 R179 R180 R181 R182 R183 R184 R185 R186 R187 R188 R189 R190 R191 R192 R193 R194 R195 R196 R197 R198 R199 R200 TP43 TP44 TP45 TP46 TP47 TP48 TP49 TP50 TP51 TP52 TP53 U5
component class PMP31236RevA_LS_U: C91 C92 C93 C94 C95 C96 C97 C98 C99 C100 C101 C102 C103 C104 C105 C106 C107 C108 C109 C110 C111 C112 C113 C114 C115 C116 C117 C118 C119 C120 D19 D20 D21 D22 D23 D24 ll Q4 R115 R116 R117 R118 R119 R120 R121 R122 R123 R124 R125 R126 R127 R128 R129 R130 R131 R132 R133 R134 R135 R136 R137 R138 R139 R140 R141 R142 R143 R144 R145 R146 R147 R148 R149 R150 R151 R152 R153 R154 R155 R156 R157 TP32 TP33 TP34 TP35 TP36 TP37 TP38 TP39 TP40 TP41 TP42 U4
component class PMP31236RevA_Interface: C241 C242 J1 J2 R292 R293 R294 R295 U13 U14
component class PMP31236RevA_HS_W: C61 C62 C63 C64 C65 C66 C67 C68 C69 C70 C71 C72 C73 C74 C75 C76 C77 C78 C79 C80 C81 C82 C83 C84 C85 C86 C87 C88 C89 C90 D13 D14 D15 D16 D17 D18 Q3 R77 R78 R79 R80 R81 R82 R83 R84 R85 R86 R87 R88 R89 R90 R91 R92 R93 R94 R95 R96 R97 R98 R99 R100 R101 R102 R103 R104 R105 R106 R107 R108 R109 R110 R111 R112 R113 R114 TP22 TP23 TP24 TP25 TP26 TP27 TP28 TP29 TP30 TP31 U3
component class PMP31236RevA_HS_V: C31 C32 C33 C34 C35 C36 C37 C38 C39 C40 C41 C42 C43 C44 C45 C46 C47 C48 C49 C50 C51 C52 C53 C54 C55 C56 C57 C58 C59 C60 D7 D8 D9 D10 D11 D12 ll Q2 R39 R40 R41 R42 R43 R44 R45 R46 R47 R48 R49 R50 R51 R52 R53 R54 R55 R56 R57 R58 R59 R60 R61 R62 R63 R64 R65 R66 R67 R68 R69 R70 R71 R72 R73 R74 R75 R76 TP12 TP13 TP14 TP15 TP16 TP17 TP18 TP19 TP20 TP21 U2
component class PMP31236RevA_HS_U: C1 C2 C3 C4 C5 C6 C7 C8 C9 C10 C11 C12 C13 C14 C15 C16 C17 C18 C19 C20 C21 C22 C23 C24 C25 C26 C27 C28 C29 C30 D1 D2 D3 D4 D5 D6 Q1 R1 R2 R3 R4 R5 R6 R7 R8 R9 R10 R11 R12 R13 R14 R15 R16 R17 R18 R19 R20 R21 R22 R23 R24 R25 R26 R27 R28 R29 R30 R31 R32 R33 R34 R35 R36 R37 R38 TP1 TP2 TP3 TP4 TP5 TP6 TP7 TP8 TP9 TP10 TP11 U1

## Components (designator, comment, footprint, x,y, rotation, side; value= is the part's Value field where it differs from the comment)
C1 "GRM21BR72A104KAC4L" 0603 793.43,491.38 r180 top value=1uF
C2 "GCM155R71H104KE02D" 0402 805,545 r0 top value=0.1uF
C3 "GRM1555C1H101JA01D" 0402 1071.38,1011.6 r0 bottom value=100pF
C4 "GRM1555C1H101JA01D" 0402 1209.47,365 r90 top value=100pF
C5 "GRM1555C1H101JA01D" 0402 1164.47,365 r90 top value=100pF
C6 "GRM1555C1H101JA01D" 0402 886.06,365 r90 top value=100pF
C7 "GRM1555C1H101JA01D" 0402 790,615 r270 top value=100pF
C8 "CGA2B3X7R1H103K050BB" 0402 780.93,1040 r270 top value=0.01uF
C9 "GCM155R71H104KE02D" 0402 1060.69,1137.25 r0 top value=0.1uF
C10 "CGA3E1X7R1V105K080AC" 0603 1191.58,1233.62 r90 top value=1uF
C11 "C0805C104K5RACAUTO" 0805_HV 870.93,2010 r0 top value=0.1uF
C12 "CGA2B3X7R1H103K050BB" 0402 1310,1235 r0 top value=0.01uF
C13 "GRM1555C1H101JA01D" 0402 1310,1145.87 r0 top value=100pF
C14 "GRM1555C1H101JA01D" 0402 1310,1097.84 r0 top value=100pF
C15 "GCM1555C1H100JA16D" 0402 1254.47,365 r270 top value=10pF
C16 "GCM1555C1H100JA16D" 0402 1344.47,365 r270 top value=10pF
C17 "GCM1555C1H100JA16D" 0402 1389.47,365 r270 top value=10pF
C18 "GCM1555C1H100JA16D" 0402 1299.47,365 r270 top value=10pF
C19 "GRM1555C1H101JA01D" 0402 1069.76,365 r270 top value=100pF
C20 "GRM1555C1H101JA01D" 0402 1117,365 r270 top value=100pF
C21 "GRM1555C1H101JA01D" 0402 932.51,365 r270 top value=100pF
C22 "GRM1555C1H101JA01D" 0402 977.51,365 r270 top value=100pF
C23 "GRM1555C1H101JA01D" 0402 1022.51,365 r270 top value=100pF
C24 "CGA5L1X7R1V106M160AC" 1206_190 1059.9,1500 r0 top value=10uF
C25 "GCM155R71H104KE02D" 0402 1125,1170 r0 top value=0.1uF
C26 "GCM155R71H104KE02D" 0402 1000,1190 r180 top value=0.1uF
C27 "CGA4J3X7R1H225K125AB" 0805_HV 894.55,1389.34 r270 top value=2.2uF
C28 "CGA5L1X7R1V106M160AC" 1206_190 1059.9,1308.82 r180 top value=10uF
C29 "GCM155R71H104KE02D" 0402 1000,1235 r180 top value=0.1uF
C30 "CGA5L1X7R1V106M160AC" 1206_190 1057.8,1405 r180 top value=10uF
C31 "GRM21BR72A104KAC4L" 0603 2573.62,450 r180 top value=1uF
C32 "GCM155R71H104KE02D" 0402 2608.05,502.87 r0 top value=0.1uF
C33 "GRM1555C1H101JA01D" 0402 2862.9,974.06 r0 bottom value=100pF
C34 "GRM1555C1H101JA01D" 0402 2908.05,330 r90 top value=100pF
C35 "GRM1555C1H101JA01D" 0402 2858.05,330 r90 top value=100pF
C36 "GRM1555C1H101JA01D" 0402 2588.62,330 r90 top value=100pF
C37 "GRM1555C1H101JA01D" 0402 2565,570 r270 top value=100pF
C38 "CGA2B3X7R1H103K050BB" 0402 2564.65,1003.96 r270 top value=0.01uF
C39 "GCM155R71H104KE02D" 0402 2817.62,1102.76 r0 top value=0.1uF
C40 "CGA3E1X7R1V105K080AC" 0603 2942.55,1150 r90 top value=1uF
C41 "C0805C104K5RACAUTO" 0805_HV 2728.05,2042.4 r0 top value=0.1uF
C42 "CGA2B3X7R1H103K050BB" 0402 2961.6,1246.76 r180 top value=0.01uF
C43 "GRM1555C1H101JA01D" 0402 3085,1103.62 r0 top value=100pF
C44 "GRM1555C1H101JA01D" 0402 3085,1058.84 r0 top value=100pF
C45 "GCM1555C1H100JA16D" 0402 3003.05,330 r270 top value=10pF
C46 "GCM1555C1H100JA16D" 0402 3092.97,330 r270 top value=10pF
C47 "GCM1555C1H100JA16D" 0402 3140.22,330 r270 top value=10pF
C48 "GCM1555C1H100JA16D" 0402 3048.05,330 r270 top value=10pF
C49 "GRM1555C1H101JA01D" 0402 2768.05,330 r270 top value=100pF
C50 "GRM1555C1H101JA01D" 0402 2813.05,330 r270 top value=100pF
C51 "GRM1555C1H101JA01D" 0402 2633.05,330 r270 top value=100pF
C52 "GRM1555C1H101JA01D" 0402 2678.05,330 r270 top value=100pF
C53 "GRM1555C1H101JA01D" 0402 2723.05,330 r270 top value=100pF
C54 "CGA5L1X7R1V106M160AC" 1206_190 2819.86,1455 r0 top value=10uF
C55 "GCM155R71H104KE02D" 0402 2858.05,1162.93 r0 top value=0.1uF
C56 "GCM155R71H104KE02D" 0402 2772.62,1147.76 r180 top value=0.1uF
C57 "CGA4J3X7R1H225K125AB" 0805_HV 2678.13,1281.76 r270 top value=2.2uF
C58 "CGA5L1X7R1V106M160AC" 1206_190 2819.86,1264.25 r180 top value=10uF
C59 "GCM155R71H104KE02D" 0402 2772.62,1191.38 r180 top value=0.1uF
C60 "CGA5L1X7R1V106M160AC" 1206_190 2819.86,1360 r180 top value=10uF
C61 "GRM21BR72A104KAC4L" 0603 4830,456.81 r180 top value=1uF
C62 "GCM155R71H104KE02D" 0402 4840,510 r0 top value=0.1uF
C63 "GRM1555C1H101JA01D" 0402 5179.41,972.22 r0 bottom value=100pF
C64 "GRM1555C1H101JA01D" 0402 5225,395 r90 top value=100pF
C65 "GRM1555C1H101JA01D" 0402 5180,395 r90 top value=100pF
C66 "GRM1555C1H101JA01D" 0402 4908.35,395 r90 top value=100pF
C67 "GRM1555C1H101JA01D" 0402 4885,580 r270 top value=100pF
C68 "CGA2B3X7R1H103K050BB" 0402 4890,1013.19 r270 top value=0.01uF
C69 "GCM155R71H104KE02D" 0402 5135,1128.62 r0 top value=0.1uF
C70 "CGA3E1X7R1V105K080AC" 0603 5310.61,1161.03 r0 top value=1uF
C71 "C0805C104K5RACAUTO" 0805_HV 4615,2015 r0 top value=0.1uF
C72 "CGA2B3X7R1H103K050BB" 0402 5385,1150 r90 top value=0.01uF
C73 "GRM1555C1H101JA01D" 0402 5475,1140 r90 top value=100pF
C74 "GRM1555C1H101JA01D" 0402 5609.61,1140 r90 top value=100pF
C75 "GCM1555C1H100JA16D" 0402 5270,395 r270 top value=10pF
C76 "GCM1555C1H100JA16D" 0402 5360,395 r270 top value=10pF
C77 "GCM1555C1H100JA16D" 0402 5405,395 r270 top value=10pF
C78 "GCM1555C1H100JA16D" 0402 5315,395 r270 top value=10pF
C79 "GRM1555C1H101JA01D" 0402 5090,395 r270 top value=100pF
C80 "GRM1555C1H101JA01D" 0402 5135,395 r270 top value=100pF
C81 "GRM1555C1H101JA01D" 0402 4955,395 r270 top value=100pF
C82 "GRM1555C1H101JA01D" 0402 5000,395 r270 top value=100pF
C83 "GRM1555C1H101JA01D" 0402 5045,395 r270 top value=100pF
C84 "CGA5L1X7R1V106M160AC" 1206_190 5056.38,1355 r0 top value=10uF
C85 "GCM155R71H104KE02D" 0402 5217.68,1123.62 r0 top value=0.1uF
C86 "GCM155R71H104KE02D" 0402 5115,1178.62 r180 top value=0.1uF
C87 "CGA4J3X7R1H225K125AB" 0805_HV 4976.46,1230 r270 top value=2.2uF
C88 "CGA5L1X7R1V106M160AC" 1206_190 5259.92,1260 r0 top value=10uF
C89 "GCM155R71H104KE02D" 0402 5115,1223.62 r180 top value=0.1uF
C90 "CGA5L1X7R1V106M160AC" 1206_190 5259.92,1355 r0 top value=10uF
C91 "GRM21BR72A104KAC4L" 0603 520,3365 r90 top value=1uF
C92 "GCM155R71H104KE02D" 0402 575,3355 r270 top value=0.1uF
C93 "GRM1555C1H101JA01D" 0402 1046.73,3067.97 r270 bottom value=100pF
C94 "GRM1555C1H101JA01D" 0402 355,3020 r0 top value=100pF
C95 "GRM1555C1H101JA01D" 0402 355,3065 r0 top value=100pF
C96 "GRM1555C1H101JA01D" 0402 355,3345 r0 top value=100pF
C97 "GRM1555C1H101JA01D" 0402 640,3380 r180 top value=100pF
C98 "CGA2B3X7R1H103K050BB" 0402 1120,3345 r180 top value=0.01uF
C99 "GCM155R71H104KE02D" 0402 1188.5,3140.43 r270 top value=0.1uF
C100 "CGA3E1X7R1V105K080AC" 0603 1260,2970.87 r0 top value=1uF
C101 "C0805C104K5RACAUTO" 0805_HV 1435,3600 r180 top value=0.1uF
C102 "GCM155R71H104KE02D" 0402 1348.75,2942.76 r90 top value=0.1uF
C103 "GRM1555C1H101JA01D" 0402 1485,2942.83 r90 top value=100pF
C104 "GRM1555C1H101JA01D" 0402 1580,2942.83 r90 top value=100pF
C105 "GCM1555C1H100JA16D" 0402 355,2975 r180 top value=10pF
C106 "GCM1555C1H100JA16D" 0402 355,2885 r180 top value=10pF
C107 "GCM1555C1H100JA16D" 0402 355,2840 r180 top value=10pF
C108 "GCM1555C1H100JA16D" 0402 355,2930 r180 top value=10pF
C109 "GRM1555C1H101JA01D" 0402 355,3157.24 r180 top value=100pF
C110 "GRM1555C1H101JA01D" 0402 355,3110 r180 top value=100pF
C111 "GRM1555C1H101JA01D" 0402 355,3300 r180 top value=100pF
C112 "GRM1555C1H101JA01D" 0402 355,3251.73 r180 top value=100pF
C113 "GRM1555C1H101JA01D" 0402 355,3204.49 r180 top value=100pF
C114 "CGA5L1X7R1V106M160AC" 1206_190 1505,3120 r270 top value=10uF
C115 "GCM155R71H104KE02D" 0402 1175,3041.38 r270 top value=0.1uF
C116 "GCM155R71H104KE02D" 0402 1235,3155.43 r90 top value=0.1uF
C117 "CGA4J3X7R1H225K125AB" 0805_HV 1455,3260 r180 top value=2.2uF
C118 "CGA5L1X7R1V106M160AC" 1206_190 1310,3120 r90 top value=10uF
C119 "GCM155R71H104KE02D" 0402 1226.5,3051.38 r90 top value=0.1uF
C120 "CGA5L1X7R1V106M160AC" 1206_190 1408.27,3120 r90 top value=10uF
C121 "GRM21BR72A104KAC4L" 0603 3208.66,4897.83 r0 top value=1uF
C122 "GCM155R71H104KE02D" 0402 3195,4845 r180 top value=0.1uF
C123 "GRM1555C1H101JA01D" 0402 2882.71,4370.02 r180 bottom value=100pF
C124 "GRM1555C1H101JA01D" 0402 2825,4995 r270 top value=100pF
C125 "GRM1555C1H101JA01D" 0402 2870,4995 r270 top value=100pF
C126 "GRM1555C1H101JA01D" 0402 3145,4995 r270 top value=100pF
C127 "GRM1555C1H101JA01D" 0402 3170,4775 r90 top value=100pF
C128 "CGA2B3X7R1H103K050BB" 0402 3083.54,4215 r0 top value=0.01uF
C129 "GCM155R71H104KE02D" 0402 2925,4235 r180 top value=0.1uF
C130 "CGA3E1X7R1V105K080AC" 0603 2726.61,4156.46 r270 top value=1uF
C131 "C0805C104K5RACAUTO" 0805_HV 3285,3595 r180 top value=0.1uF
C132 "GCM155R71H104KE02D" 0402 2625,4173.32 r180 top value=0.1uF
C133 "GRM1555C1H101JA01D" 0402 2625,4264.91 r180 top value=100pF
C134 "GRM1555C1H101JA01D" 0402 2625,4311.24 r180 top value=100pF
C135 "GCM1555C1H100JA16D" 0402 2780,4995 r90 top value=10pF
C136 "GCM1555C1H100JA16D" 0402 2687.76,4995 r90 top value=10pF
C137 "GCM1555C1H100JA16D" 0402 2643.15,4995 r90 top value=10pF
C138 "GCM1555C1H100JA16D" 0402 2735,4995 r90 top value=10pF
C139 "GRM1555C1H101JA01D" 0402 2965,4995 r90 top value=100pF
C140 "GRM1555C1H101JA01D" 0402 2917.76,4995 r90 top value=100pF
C141 "GRM1555C1H101JA01D" 0402 3100,4995 r90 top value=100pF
C142 "GRM1555C1H101JA01D" 0402 3055,4995 r90 top value=100pF
C143 "GRM1555C1H101JA01D" 0402 3010,4995 r90 top value=100pF
C144 "CGA5L1X7R1V106M160AC" 1206_190 2803.5,4060 r90 top value=10uF
C145 "GCM155R71H104KE02D" 0402 2835,4245 r180 top value=0.1uF
C146 "GCM155R71H104KE02D" 0402 2930,4190 r0 top value=0.1uF
C147 "CGA4J3X7R1H225K125AB" 0805_HV 2865.32,3890 r0 top value=2.2uF
C148 "CGA5L1X7R1V106M160AC" 1206_190 2942.24,4075 r0 top value=10uF
C149 "GCM155R71H104KE02D" 0402 2930,4145 r0 top value=0.1uF
C150 "CGA5L1X7R1V106M160AC" 1206_190 2942.24,3980 r0 top value=10uF
C151 "GRM21BR72A104KAC4L" 0603 5697.99,4886.69 r0 top value=1uF
C152 "GCM155R71H104KE02D" 0402 5687.99,4828.31 r180 top value=0.1uF
C153 "GRM1555C1H101JA01D" 0402 5399.82,4355 r180 bottom value=100pF
C154 "GRM1555C1H101JA01D" 0402 5335,4995 r270 top value=100pF
C155 "GRM1555C1H101JA01D" 0402 5380,4995 r270 top value=100pF
C156 "GRM1555C1H101JA01D" 0402 5650,4995 r270 top value=100pF
C157 "GRM1555C1H101JA01D" 0402 5692.99,4760 r90 top value=100pF
C158 "CGA2B3X7R1H103K050BB" 0402 5687.99,4335 r90 top value=0.01uF
C159 "GCM155R71H104KE02D" 0402 5449.8,4240 r180 top value=0.1uF
C160 "CGA3E1X7R1V105K080AC" 0603 5284.52,4168.12 r270 top value=1uF
C161 "C0805C104K5RACAUTO" 0805_HV 5142.91,3600 r180 top value=0.1uF
C162 "GCM155R71H104KE02D" 0402 5161.5,4155 r180 top value=0.1uF
C163 "GRM1555C1H101JA01D" 0402 5161.5,4290.19 r180 top value=100pF
C164 "GRM1555C1H101JA01D" 0402 5161.5,4337.19 r180 top value=100pF
C165 "GCM1555C1H100JA16D" 0402 5290,4995 r90 top value=10pF
C166 "GCM1555C1H100JA16D" 0402 5200,4995 r90 top value=10pF
C167 "GCM1555C1H100JA16D" 0402 5155,4995 r90 top value=10pF
C168 "GCM1555C1H100JA16D" 0402 5245,4995 r90 top value=10pF
C169 "GRM1555C1H101JA01D" 0402 5470,4995 r90 top value=100pF
C170 "GRM1555C1H101JA01D" 0402 5425,4995 r90 top value=100pF
C171 "GRM1555C1H101JA01D" 0402 5605,4995 r90 top value=100pF
C172 "GRM1555C1H101JA01D" 0402 5560,4995 r90 top value=100pF
C173 "GRM1555C1H101JA01D" 0402 5515,4995 r90 top value=100pF
C174 "CGA5L1X7R1V106M160AC" 1206_190 5206.69,4065 r0 top value=10uF
C175 "GCM155R71H104KE02D" 0402 5355.31,4240 r180 top value=0.1uF
C176 "GCM155R71H104KE02D" 0402 5457.73,4192.5 r0 top value=0.1uF
C177 "CGA4J3X7R1H225K125AB" 0805_HV 5593.11,4167.62 r180 top value=2.2uF
C178 "CGA5L1X7R1V106M160AC" 1206_190 5422.56,4076.89 r0 top value=10uF
C179 "GCM155R71H104KE02D" 0402 5457.73,4146.09 r0 top value=0.1uF
C180 "CGA5L1X7R1V106M160AC" 1206_190 5422.56,3980 r0 top value=10uF
C181 "GRM188R71H102KA01D" 0603 1495,1193.33 r180 top value=1000pF
C182 "GRM155R71H104ME14D" 0402 1672.76,1078.62 r0 top value=0.1uF
C183 "TMK325B7226MM-PR" 1210_270 1682.76,1164.25 r0 top value=22uF
C184 "GRM32ER71H106KA12L" 1210_270 1630,353.74 r270 top value=10uF
C185 "GRM155R71H104ME14D" 0402 1720,380 r270 top value=0.1uF
C186 "GRM188R72A682KA01D" 0603 1668.5,502.87 r0 top value=6800pF
C187 "GRM155R71H104ME14D" 0402 1885.85,1078.62 r0 top value=0.1uF
C188 "TMK325B7226MM-PR" 1210_270 1873.72,1164.25 r0 top value=22uF
C189 "GRM188R71H102KA01D" 0603 2055,1205 r180 top value=1000pF
C190 "GRM188R71H223KA01D" 0603 1770,185 r270 top value=0.022uF
C191 "GRM188R71H102KA01D" 0603 1235,2719.45 r90 top value=1000pF
C192 "GRM155R71H104ME14D" 0402 1118.5,2545 r270 top value=0.1uF
C193 "TMK325B7226MM-PR" 1210_270 1205,2535 r270 top value=22uF
C194 "GRM32ER71H106KA12L" 1210_270 390,2585 r180 top value=10uF
C195 "GRM155R71H104ME14D" 0402 404.8,2492.91 r180 top value=0.1uF
C196 "GRM188R72A682KA01D" 0603 545,2530 r270 top value=6800pF
C197 "GRM155R71H104ME14D" 0402 1118.5,2328.62 r270 top value=0.1uF
C198 "TMK325B7226MM-PR" 1210_270 1205,2338.62 r270 top value=22uF
C199 "GRM188R71H102KA01D" 0603 1250,2155 r90 top value=1000pF
C200 "GRM188R71H223KA01D" 0603 227.48,2498.5 r90 top value=0.022uF
C201 "GRM188R71H102KA01D" 0603 3273.05,1150.12 r180 top value=1000pF
C202 "GRM155R71H104ME14D" 0402 3450.06,1036.61 r0 top value=0.1uF
C203 "TMK325B7226MM-PR" 1210_270 3455.06,1130 r0 top value=22uF
C204 "GRM32ER71H106KA12L" 1210_270 3395,331.5 r270 top value=10uF
C205 "GRM155R71H104ME14D" 0402 3500,327.56 r270 top value=0.1uF
C206 "GRM188R72A682KA01D" 0603 3447.3,460.12 r0 top value=6800pF
C207 "GRM155R71H104ME14D" 0402 3660,1036.61 r0 top value=0.1uF
C208 "TMK325B7226MM-PR" 1210_270 3650,1130 r0 top value=22uF
C209 "GRM188R71H102KA01D" 0603 3840,1150 r180 top value=1000pF
C210 "GRM188R71H223KA01D" 0603 3510,165 r270 top value=0.022uF
C211 "GRM188R71H102KA01D" 0603 3930,4191.38 r0 top value=1000pF
C212 "GRM155R71H104ME14D" 0402 3750,4315 r180 top value=0.1uF
C213 "TMK325B7226MM-PR" 1210_270 3745,4223.62 r180 top value=22uF
C214 "GRM32ER71H106KA12L" 1210_270 3805,5035 r90 top value=10uF
C215 "GRM155R71H104ME14D" 0402 3715,5023.62 r90 top value=0.1uF
C216 "GRM188R72A682KA01D" 0603 3725,4885 r180 top value=6800pF
C217 "GRM155R71H104ME14D" 0402 3535.63,4315 r180 top value=0.1uF
C218 "TMK325B7226MM-PR" 1210_270 3550.63,4223.62 r180 top value=22uF
C219 "GRM188R71H102KA01D" 0603 3365,4200 r0 top value=1000pF
C220 "GRM188R71H223KA01D" 0603 3667.01,5175 r0 top value=0.022uF
C221 "GRM188R71H102KA01D" 0603 5410,2145 r0 top value=1000pF
C222 "GRM155R71H104ME14D" 0402 5235,2260 r180 top value=0.1uF
C223 "TMK325B7226MM-PR" 1210_270 5228.62,2175 r180 top value=22uF
C224 "GRM32ER71H106KA12L" 1210_270 5280,2980 r90 top value=10uF
C225 "GRM155R71H104ME14D" 0402 5190.2,2985 r90 top value=0.1uF
C226 "GRM188R72A682KA01D" 0603 5230,2840 r180 top value=6800pF
C227 "GRM155R71H104ME14D" 0402 5020,2260 r180 top value=0.1uF
C228 "TMK325B7226MM-PR" 1210_270 5030,2175 r180 top value=22uF
C229 "GRM188R71H102KA01D" 0603 4840,2135 r0 top value=1000pF
C230 "GRM188R71H223KA01D" 0603 5137.87,3172.24 r90 top value=0.022uF
C231 "GRM188R71H102KA01D" 0603 4915,4190 r0 top value=1000pF
C232 "GRM155R71H104ME14D" 0402 4741.38,4310 r180 top value=0.1uF
C233 "TMK325B7226MM-PR" 1210_270 4735,4205 r180 top value=22uF
C234 "GRM32ER71H106KA12L" 1210_270 4783.5,5042.09 r90 top value=10uF
C235 "GRM155R71H104ME14D" 0402 4693.5,5027.09 r90 top value=0.1uF
C236 "GRM188R72A682KA01D" 0603 4730,4895 r180 top value=6800pF
C237 "GRM155R71H104ME14D" 0402 4525,4310 r180 top value=0.1uF
C238 "TMK325B7226MM-PR" 1210_270 4540.28,4205 r180 top value=22uF
C239 "GRM188R71H102KA01D" 0603 4355,4190 r0 top value=1000pF
C240 "GRM188R71H223KA01D" 0603 4675,5190 r0 top value=0.022uF
C241 "GRM155R71E104KE14D" 0402 1855,4740 r180 top value=0.1uF
C242 "GRM155R71E104KE14D" 0402 1648.62,4740 r180 top value=0.1uF
D1 "GB02SLT12-214" FP-GB02SLT12-214_DO-214AA-MFG 1520,1540 r180 top
D2 "BAT54WS-7-F" SOD-323 1283.55,1425 r180 top value=30V
D3 "1.5SMC530A" FP-1.5SMC530A_SMC-MFG 1355,1783.23 r180 top
D4 "1.5SMC530A" FP-1.5SMC530A_SMC-MFG 1754.47,1783.23 r180 top
D5 "MBRA340T3G" SMA 1056.38,1675 r0 top value=40V
D6 "BAT54WS-7-F" SOD-323 897.64,1540 r90 top value=30V
D7 "GB02SLT12-214" FP-GB02SLT12-214_DO-214AA-MFG 3725,1575 r270 top
D8 "BAT54WS-7-F" SOD-323 2578.86,1360 r90 top value=30V
D9 "1.5SMC530A" FP-1.5SMC530A_SMC-MFG 3170,1854.53 r180 top
D10 "1.5SMC530A" FP-1.5SMC530A_SMC-MFG 3592.91,1854.53 r180 top
D11 "MBRA340T3G" SMA 2825,1658 r0 top value=40V
D12 "BAT54WS-7-F" SOD-323 2680,1507.69 r90 top value=30V
D13 "GB02SLT12-214" FP-GB02SLT12-214_DO-214AA-MFG 5367.49,1572.6 r270 top
D14 "BAT54WS-7-F" SOD-323 5118.19,1480 r0 top value=30V
D15 "1.5SMC530A" FP-1.5SMC530A_SMC-MFG 5047.32,1849.53 r180 top
D16 "1.5SMC530A" FP-1.5SMC530A_SMC-MFG 5464.61,1869.53 r180 top
D17 "MBRA340T3G" SMA 4785,1625 r0 top value=40V
D18 "BAT54WS-7-F" SOD-323 4935,1480 r180 top value=30V
D19 "GB02SLT12-214" FP-GB02SLT12-214_DO-214AA-MFG 1541.56,2570 r90 top
D20 "BAT54WS-7-F" SOD-323 1715,2955 r90 top value=30V
D21 "1.5SMC530A" FP-1.5SMC530A_SMC-MFG 1970,2960 r90 top
D22 "1.5SMC530A" FP-1.5SMC530A_SMC-MFG 1870,2545 r90 top
D23 "MBRA340T3G" SMA 1970,3545 r270 top value=40V
D24 "BAT54WS-7-F" SOD-323 1495,3415 r90 top value=30V
D25 "GB02SLT12-214" FP-GB02SLT12-214_DO-214AA-MFG 3290,2855 r90 top
D26 "BAT54WS-7-F" SOD-323 2685,4010 r90 top value=30V
D27 "1.5SMC530A" FP-1.5SMC530A_SMC-MFG 3520,3045 r90 top
D28 "1.5SMC530A" FP-1.5SMC530A_SMC-MFG 3520,2617.17 r90 top
D29 "MBRA340T3G" SMA 3200,3965 r180 top value=40V
D30 "BAT54WS-7-F" SOD-323 2890,3775 r0 top value=30V
D31 "GB02SLT12-214" FP-GB02SLT12-214_DO-214AA-MFG 4465,3492.17 r90 top
D32 "BAT54WS-7-F" SOD-323 5250,3940 r0 top value=30V
D33 "1.5SMC530A" FP-1.5SMC530A_SMC-MFG 4465,3148.62 r90 top
D34 "1.5SMC530A" FP-1.5SMC530A_SMC-MFG 4465,2760 r90 top
D35 "MBRA340T3G" SMA 5514.92,3756.1 r0 top value=40V
D36 "BAT54WS-7-F" SOD-323 4805,3940 r270 top value=30V
D37 "PMEG6010CEH,115" SOD-123F 1539.47,1060.75 r270 top value=60V
D38 "MMSZ5248B-7-F" SOD-123 1675,1295 r0 top value=18V
D39 "BAS16D-E3-08" SOD-123 1865.85,580.75 r0 top value=100V
D40 "MMSZ4694-HE3-08" SOD-123 1877.97,1295 r0 top value=8.2V
D41 "PMEG6010CEH,115" SOD-123F 2014.47,1065.75 r90 top value=60V
D42 "PMEG6010CEH,115" SOD-123F 1095,2680 r180 top value=60V
D43 "MMSZ5248B-7-F" SOD-123 1335,2535 r270 top value=18V
D44 "BAS16D-E3-08" SOD-123 619.8,2351.02 r270 top value=100V
D45 "MMSZ4694-HE3-08" SOD-123 1335,2328.62 r270 top value=8.2V
D46 "PMEG6010CEH,115" SOD-123F 1100,2190 r0 top value=60V
D47 "PMEG6010CEH,115" SOD-123F 3307.3,1020.12 r270 top value=60V
D48 "MMSZ5248B-7-F" SOD-123 3455,1265 r0 top value=18V
D49 "BAS16D-E3-08" SOD-123 3643.05,540.12 r0 top value=100V
D50 "MMSZ4694-HE3-08" SOD-123 3653.68,1265 r0 top value=8.2V
D51 "PMEG6010CEH,115" SOD-123F 3802.3,1020.12 r90 top value=60V
D52 "PMEG6010CEH,115" SOD-123F 3890,4330 r90 top value=60V
D53 "MMSZ5248B-7-F" SOD-123 3735,4090 r180 top value=18V
D54 "BAS16D-E3-08" SOD-123 3550,4810 r180 top value=100V
D55 "MMSZ4694-HE3-08" SOD-123 3541.38,4090 r180 top value=8.2V
D56 "PMEG6010CEH,115" SOD-123F 3405,4330.37 r270 top value=60V
D57 "PMEG6010CEH,115" SOD-123F 5370,2280 r90 top value=60V
D58 "MMSZ5248B-7-F" SOD-123 5236.14,2045 r180 top value=18V
D59 "BAS16D-E3-08" SOD-123 5040,2755 r180 top value=100V
D60 "MMSZ4694-HE3-08" SOD-123 5023.5,2045 r180 top value=8.2V
D61 "PMEG6010CEH,115" SOD-123F 4880,2270 r270 top value=60V
D62 "PMEG6010CEH,115" SOD-123F 4875,4325 r90 top value=60V
D63 "MMSZ5248B-7-F" SOD-123 4730,4075 r180 top value=18V
D64 "BAS16D-E3-08" SOD-123 4545,4810 r180 top value=100V
D65 "MMSZ4694-HE3-08" SOD-123 4535,4075 r180 top value=8.2V
D66 "PMEG6010CEH,115" SOD-123F 4400,4323.5 r270 top value=60V
J1 "254589" FP-254589_CONN_HDR32-MFG 665,5058.27 r180 top
J2 "HTSW-103-09-G-S" Samtec_HTSW-103-09-x-S 2280,5190 r180 top
J3 "0405-0-15-15-34-27-04-0" FP-0405-0-15-15-34-27-04-0_HDR1-MFG 3915.35,1748.23 r180 bottom
J4 "0405-0-15-15-34-27-04-0" FP-0405-0-15-15-34-27-04-0_HDR1-MFG 2647.64,1854.53 r180 bottom
J5 "0405-0-15-15-34-27-04-0" FP-0405-0-15-15-34-27-04-0_HDR1-MFG 1517.72,3756.1 r180 bottom
J6 "0405-0-15-15-34-27-04-0" FP-0405-0-15-15-34-27-04-0_HDR1-MFG 5820.87,2456.89 r180 bottom
J7 "0405-0-15-15-34-27-04-0" FP-0405-0-15-15-34-27-04-0_HDR1-MFG 5059.06,3756.1 r180 bottom
J8 "0405-0-15-15-34-27-04-0" FP-0405-0-15-15-34-27-04-0_HDR1-MFG 5765.75,1748.23 r180 bottom
J9 "0405-0-15-15-34-27-04-0" FP-0405-0-15-15-34-27-04-0_HDR1-MFG 2064.96,1748.23 r180 bottom
J10 "0405-0-15-15-34-27-04-0" FP-0405-0-15-15-34-27-04-0_HDR1-MFG 2807.09,1854.53 r180 bottom
J11 "0405-0-15-15-34-27-04-0" FP-0405-0-15-15-34-27-04-0_HDR1-MFG 1358.27,3756.1 r180 bottom
J12 "0405-0-15-15-34-27-04-0" FP-0405-0-15-15-34-27-04-0_HDR1-MFG 4657.48,1854.53 r180 bottom
J13 "0405-0-15-15-34-27-04-0" FP-0405-0-15-15-34-27-04-0_HDR1-MFG 5218.5,3756.1 r180 bottom
J14 "0405-0-15-15-34-27-04-0" FP-0405-0-15-15-34-27-04-0_HDR1-MFG 2570.87,3756.1 r180 bottom
J15 "0405-0-15-15-34-27-04-0" FP-0405-0-15-15-34-27-04-0_HDR1-MFG 956.69,1854.53 r180 bottom
J16 "0405-0-15-15-34-27-04-0" FP-0405-0-15-15-34-27-04-0_HDR1-MFG 3368.11,3756.1 r180 bottom
J17 "0405-0-15-15-34-27-04-0" FP-0405-0-15-15-34-27-04-0_HDR1-MFG 2120.08,2456.89 r180 bottom
J18 "0405-0-15-15-34-27-04-0" FP-0405-0-15-15-34-27-04-0_HDR1-MFG 3970.47,2161.61 r180 bottom
J19 "0405-0-15-15-34-27-04-0" FP-0405-0-15-15-34-27-04-0_HDR1-MFG 5820.87,2161.61 r180 bottom
J20 "0405-0-15-15-34-27-04-0" FP-0405-0-15-15-34-27-04-0_HDR1-MFG 720.47,3756.1 r180 bottom
J21 "0405-0-15-15-34-27-04-0" FP-0405-0-15-15-34-27-04-0_HDR1-MFG 797.24,1854.53 r180 bottom
J22 "0405-0-15-15-34-27-04-0" FP-0405-0-15-15-34-27-04-0_HDR1-MFG 3208.66,3756.1 r180 bottom
J23 "0405-0-15-15-34-27-04-0" FP-0405-0-15-15-34-27-04-0_HDR1-MFG 3970.47,2456.89 r180 bottom
J24 "0405-0-15-15-34-27-04-0" FP-0405-0-15-15-34-27-04-0_HDR1-MFG 2120.08,2161.61 r180 bottom
J25 "0405-0-15-15-34-27-04-0" FP-0405-0-15-15-34-27-04-0_HDR1-MFG 4498.03,1854.53 r180 bottom
J26 "0405-0-15-15-34-27-04-0" FP-0405-0-15-15-34-27-04-0_HDR1-MFG 4421.26,3756.1 r180 bottom
Q1 "SI2318CDS-T1-GE3" SOT-23 760,1677.76 r90 top value=40V
Q2 "SI2318CDS-T1-GE3" SOT-23 2572.4,1697.24 r90 top value=40V
Q3 "SI2318CDS-T1-GE3" SOT-23 4498.03,1660.55 r90 top value=40V
Q4 "SI2318CDS-T1-GE3" SOT-23 1730,3665 r90 top value=40V
Q5 "SI2318CDS-T1-GE3" SOT-23 3565,3780 r180 top value=40V
Q6 "SI2318CDS-T1-GE3" SOT-23 4875,3730 r0 top value=40V
Q7 "FS660R08A6P2FBBPSA1" FP-FS660R08A6P2FBBPSA1_PTH_MD_1554MM5_100MM5-MFG 3208.66,2903.74 r0 bottom locked value=750V
R1 "CRCW040210R0JNED" 0402 790,440 r0 top value=10
R2 "CRCW040247K0JNED" 0402 785,365 r90 top value=47k
R3 "CRCW040247K0JNED" 0402 700,615 r270 top value=47k
R4 "CRCW06031K00FKEA" 0603 1326.71,1530 r90 top value=1.00k
R5 "CRCW0402100RJNED" 0402 1209.47,365.75 r90 bottom value=100
R6 "CRCW060333R0JNEA" 0603 716.93,1050 r90 top value=33
R7 "CRCW0402100RJNED" 0402 1164.47,365.75 r90 bottom value=100
R8 "CRCW0402100RJNED" 0402 840,365 r90 top value=100
R9 "CRCW080510R0FKEA" 0805_HV 1385,1635 r90 bottom value=10.0
R10 "CRCW080510R0FKEA" 0805_HV 1300,1635 r90 bottom value=10.0
R11 "CRCW0402100RJNED" 0402 745,615 r270 top value=100
R12 "CRCW08058R45FKEA" 0805_HV 1220,1635 r90 bottom value=8.45
R13 "CRCW08058R45FKEA" 0805_HV 1140,1635 r90 bottom value=8.45
R14 "CRCW0402100RJNED" 0402 932.51,365.75 r90 bottom value=100
R15 "CRCW0402100RJNED" 0402 977.51,365.75 r90 bottom value=100
R16 "CRCW080520R0FKEA" 0805_HV 1060,1635 r90 bottom value=20.0
R17 "CRCW080520R0FKEA" 0805_HV 980,1635 r90 bottom value=20.0
R18 "CRCW0402100RJNED" 0402 1022.51,365.75 r90 bottom value=100
R19 "CRCW040210K0FKED" 0402 1091.89,250 r180 bottom value=10.0k
R20 "CRCW080518R2FKEA" 0805_HV 895,1635 r90 bottom value=18.2
R21 "CRCW06030000Z0EA" 0603 751.93,1175.81 r180 top value=0
R22 "CRCW0402100RJNED" 0402 1069.76,365.75 r90 bottom value=100
R23 "CRCW080518R2FKEA" 0805_HV 815,1635 r90 bottom value=18.2
R24 "CRCW06030000Z0EA" 0603 760,1500 r0 top value=0
R25 "CRCW060310K0JNEA" 0603 880.46,1689.95 r270 top value=10k
R26 "CRCW0402100RJNED" 0402 1117,365.75 r90 bottom value=100
R27 "CRCW060310K0JNEA" 0603 760,1560 r180 top value=10k
R28 "CRCW0402100RJNED" 0402 1254.47,365.75 r90 bottom value=100
R29 "CRCW0402100RFKED" 0402 1416.23,1316.72 r90 top value=100
R30 "CRCW040210K0FKED" 0402 1140,295 r180 bottom value=10.0k
R31 "CRCW0402100RJNED" 0402 1344.47,365.75 r90 bottom value=100
R32 "CRCW0402100RFKED" 0402 1310,1006.62 r0 top value=100
R33 "CRCW04020000Z0ED" 0402 1246.68,1255.96 r90 top value=0
R34 "CRCW0402100RJNED" 0402 1389.47,365.75 r90 bottom value=100
R35 "CRCW0402100RJNED" 0402 1299.47,365.75 r90 bottom value=100
R36 "CRCW04026K04FKED" 0402 1310,1282.6 r180 top value=6.04k
R37 "CRCW040210K0FKED" 0402 1310,1190 r180 top value=10.0k
R38 "CRCW040210K0FKED" 0402 1310,1050.63 r180 top value=10.0k
R39 "CRCW040210R0JNED" 0402 2547.13,398.54 r0 top value=10
R40 "CRCW040247K0JNED" 0402 2500,330 r90 top value=47k
R41 "CRCW040247K0JNED" 0402 2475,570 r270 top value=47k
R42 "CRCW06031K00FKEA" 0603 2520.18,1230.12 r270 top value=1.00k
R43 "CRCW0402100RJNED" 0402 2955,330 r90 top value=100
R44 "CRCW060333R0JNEA" 0603 2507.05,1008.96 r90 top value=33
R45 "CRCW0402100RJNED" 0402 2858.05,330.12 r90 bottom value=100
R46 "CRCW0402100RJNED" 0402 2545,330 r90 top value=100
R47 "CRCW080510R0FKEA" 0805_HV 3250,1625 r90 bottom value=10.0
R48 "CRCW080510R0FKEA" 0805_HV 3164.43,1625 r90 bottom value=10.0
R49 "CRCW0402100RJNED" 0402 2520,570 r270 top value=100
R50 "CRCW08058R45FKEA" 0805_HV 3080,1625 r90 bottom value=8.45
R51 "CRCW08058R45FKEA" 0805_HV 2995,1625 r90 bottom value=8.45
R52 "CRCW0402100RJNED" 0402 2633.05,330.12 r90 bottom value=100
R53 "CRCW0402100RJNED" 0402 2678.05,330.12 r90 bottom value=100
R54 "CRCW080520R0FKEA" 0805_HV 2910,1625 r90 bottom value=20.0
R55 "CRCW080520R0FKEA" 0805_HV 2830,1625 r90 bottom value=20.0
R56 "CRCW0402100RJNED" 0402 2723.05,330.12 r90 bottom value=100
R57 "CRCW040210K0FKED" 0402 2786.44,215 r180 bottom value=10.0k
R58 "CRCW080518R2FKEA" 0805_HV 2745,1625 r90 bottom value=18.2
R59 "CRCW06030000Z0EA" 0603 2549.57,1148.03 r180 top value=0
R60 "CRCW0402100RJNED" 0402 2768.05,330.12 r90 bottom value=100
R61 "CRCW080518R2FKEA" 0805_HV 2660,1625 r90 bottom value=18.2
R62 "CRCW06030000Z0EA" 0603 2460,1540 r270 top value=0
R63 "CRCW060310K0JNEA" 0603 2728.05,2115 r180 top value=10k
R64 "CRCW0402100RJNED" 0402 2813.05,330.12 r90 bottom value=100
R65 "CRCW060310K0JNEA" 0603 2572.4,1575 r180 top value=10k
R66 "CRCW0402100RJNED" 0402 3003.05,330.12 r90 bottom value=100
R67 "CRCW0402100RFKED" 0402 3085,1194.4 r0 top value=100
R68 "CRCW040210K0FKED" 0402 2840,260 r180 bottom value=10.0k
R69 "CRCW0402100RJNED" 0402 3092.97,330.12 r90 bottom value=100
R70 "CRCW0402100RFKED" 0402 3085,965 r0 top value=100
R71 "CRCW04020000Z0ED" 0402 3030.63,1269.07 r90 top value=0
R72 "CRCW0402100RJNED" 0402 3140.22,330.12 r90 bottom value=100
R73 "CRCW0402100RJNED" 0402 3048.05,330.12 r90 bottom value=100
R74 "CRCW04026K04FKED" 0402 2961.6,1292.42 r0 top value=6.04k
R75 "CRCW040210K0FKED" 0402 3085,1150 r180 top value=10.0k
R76 "CRCW040210K0FKED" 0402 3085,1012.52 r180 top value=10.0k
R77 "CRCW040210R0JNED" 0402 4861.5,373.35 r90 top value=10
R78 "CRCW040247K0JNED" 0402 4864.27,395 r270 bottom value=47k
R79 "CRCW040247K0JNED" 0402 4795,580 r270 top value=47k
R80 "CRCW06031K00FKEA" 0603 5194.06,1570 r0 top value=1.00k
R81 "CRCW0402100RJNED" 0402 5225,395 r90 bottom value=100
R82 "CRCW060333R0JNEA" 0603 4830,1018.19 r90 top value=33
R83 "CRCW0402100RJNED" 0402 5180,395 r90 bottom value=100
R84 "CRCW0402100RJNED" 0402 4908.35,395 r90 bottom value=100
R85 "CRCW080510R0FKEA" 0805_HV 5250,1625 r90 bottom value=10.0
R86 "CRCW080510R0FKEA" 0805_HV 5335,1625 r90 bottom value=10.0
R87 "CRCW0402100RJNED" 0402 4840,580 r270 top value=100
R88 "CRCW08058R45FKEA" 0805_HV 5085,1625 r90 bottom value=8.45
R89 "CRCW08058R45FKEA" 0805_HV 5165,1625 r90 bottom value=8.45
R90 "CRCW0402100RJNED" 0402 4955,395 r90 bottom value=100
R91 "CRCW0402100RJNED" 0402 5000,396.97 r90 bottom value=100
R92 "CRCW080520R0FKEA" 0805_HV 4995,1625 r90 bottom value=20.0
R93 "CRCW080520R0FKEA" 0805_HV 4915,1625 r90 bottom value=20.0
R94 "CRCW0402100RJNED" 0402 5045,395 r90 bottom value=100
R95 "CRCW040210K0FKED" 0402 5115,280 r180 bottom value=10.0k
R96 "CRCW080518R2FKEA" 0805_HV 4830,1625 r90 bottom value=18.2
R97 "CRCW06030000Z0EA" 0603 4890.81,1375 r90 top value=0
R98 "CRCW0402100RJNED" 0402 5090,395 r90 bottom value=100
R99 "CRCW080518R2FKEA" 0805_HV 4745,1625 r90 bottom value=18.2
R100 "CRCW06030000Z0EA" 0603 4890,1245 r270 top value=0
R101 "CRCW060310K0JNEA" 0603 4620,2085 r180 top value=10k
R102 "CRCW0402100RJNED" 0402 5135,395 r90 bottom value=100
R103 "CRCW060310K0JNEA" 0603 4498.03,1545 r180 top value=10k
R104 "CRCW0402100RJNED" 0402 5270,395 r90 bottom value=100
R105 "CRCW0402100RFKED" 0402 5565,1140 r90 top value=100
R106 "CRCW040210K0FKED" 0402 5160,325 r180 bottom value=10.0k
R107 "CRCW0402100RJNED" 0402 5360,395 r90 bottom value=100
R108 "CRCW0402100RFKED" 0402 5655,1140 r90 top value=100
R109 "CRCW04020000Z0ED" 0402 5407.03,1086.2 r0 top value=0
R110 "CRCW0402100RJNED" 0402 5405,395 r90 bottom value=100
R111 "CRCW0402100RJNED" 0402 5315,395 r90 bottom value=100
R112 "CRCW04026K04FKED" 0402 5430,1150 r270 top value=6.04k
R113 "CRCW040210K0FKED" 0402 5520,1140 r270 top value=10.0k
R114 "CRCW040210K0FKED" 0402 5700,1140 r270 top value=10.0k
R115 "CRCW040210R0JNED" 0402 464.8,3378.62 r270 top value=10
R116 "CRCW040247K0JNED" 0402 355,3389.39 r0 bottom value=47k
R117 "CRCW040247K0JNED" 0402 645,3476.06 r180 top value=47k
R118 "CRCW06031K00FKEA" 0603 1645,2810 r270 top value=1.00k
R119 "CRCW0402100RJNED" 0402 355,3020 r0 bottom value=100
R120 "CRCW060333R0JNEA" 0603 1130,3400 r0 top value=33
R121 "CRCW0402100RJNED" 0402 355,3065 r0 bottom value=100
R122 "CRCW0402100RJNED" 0402 355,3345 r0 bottom value=100
R123 "CRCW080510R0FKEA" 0805_HV 1635,3405 r90 bottom value=10.0
R124 "CRCW080510R0FKEA" 0805_HV 1555,3405 r90 bottom value=10.0
R125 "CRCW0402100RJNED" 0402 640,3428.82 r180 top value=100
R126 "CRCW08058R45FKEA" 0805_HV 1395,3405 r90 bottom value=8.45
R127 "CRCW08058R45FKEA" 0805_HV 1475,3405 r90 bottom value=8.45
R128 "CRCW0402100RJNED" 0402 355,3300 r0 bottom value=100
R129 "CRCW0402100RJNED" 0402 355,3251.73 r0 bottom value=100
R130 "CRCW0402100RJNED" 0402 355,3204.49 r0 bottom value=100
R131 "CRCW040210K0FKED" 0402 235,3135 r90 bottom value=10.0k
R132 "CRCW080520R0FKEA" 0805_HV 1230,3405 r90 bottom value=20.0
R133 "CRCW080520R0FKEA" 0805_HV 1315,3405 r90 bottom value=20.0
R134 "CRCW0402100RJNED" 0402 355,3157.24 r0 bottom value=100
R135 "CRCW080518R2FKEA" 0805_HV 1060,3405 r90 bottom value=18.2
R136 "CRCW06030000Z0EA" 0603 1230,3361.69 r90 top value=0
R137 "CRCW080518R2FKEA" 0805_HV 1145,3405 r90 bottom value=18.2
R138 "CRCW060310K0JNEA" 0603 1435,3525 r0 top value=10k
R139 "CRCW06030000Z0EA" 0603 1615,3577.24 r90 top value=0
R140 "CRCW0402100RJNED" 0402 355,3110 r0 bottom value=100
R141 "CRCW060310K0JNEA" 0603 1730,3545.75 r180 top value=10k
R142 "CRCW0402100RJNED" 0402 355,2975 r0 bottom value=100
R143 "CRCW0402100RFKED" 0402 1390,2807.83 r180 top value=100
R144 "CRCW040210K0FKED" 0402 280,3085 r90 bottom value=10.0k
R145 "CRCW0402100RJNED" 0402 355,2885 r0 bottom value=100
R146 "CRCW0402100RFKED" 0402 1535,2841.5 r270 top value=100
R147 "CRCW0402100RJNED" 0402 355,2840 r0 bottom value=100
R148 "CRCW0402100RJNED" 0402 355,2930 r0 bottom value=100
R149 "CRCW040210K0FKED" 0402 1440,2942.83 r270 top value=10.0k
R150 "CRCW040210K0FKED" 0402 1535,2942.83 r270 top value=10.0k
R151 "CRCW1206191KFKEA" 1206 2295,2025 r270 top value=191k
R152 "CRCW1206191KFKEA" 1206 2295,2215 r270 top value=191k
R153 "CRCW1206191KFKEA" 1206 2295,2405 r270 top value=191k
R154 "CRCW1206191KFKEA" 1206 2295,2595 r270 top value=191k
R155 "CRCW1206191KFKEA" 1206 2295,2785 r270 top value=191k
R156 "CRCW1206191KFKEA" 1206 2295,2975 r270 top value=191k
R157 "CRCW04023K83FKED" 0402 1393.75,2942.83 r270 top value=3.83k
R158 "CRCW040210R0JNED" 0402 3218.62,4948.8 r180 top value=10
R159 "CRCW040247K0JNED" 0402 3220,5018.62 r0 bottom value=47k
R160 "CRCW040247K0JNED" 0402 3260,4775 r90 top value=47k
R161 "CRCW06031K00FKEA" 0603 2700,3860 r270 top value=1.00k
R162 "CRCW0402100RJNED" 0402 2825,4995 r270 bottom value=100
R163 "CRCW060333R0JNEA" 0603 3083.54,4146.38 r180 top value=33
R164 "CRCW0402100RJNED" 0402 2870,4995 r270 bottom value=100
R165 "CRCW0402100RJNED" 0402 3145,4995 r270 bottom value=100
R166 "CRCW080510R0FKEA" 0805_HV 2805,4050 r270 bottom value=10.0
R167 "CRCW080510R0FKEA" 0805_HV 2725,4050 r270 bottom value=10.0
R168 "CRCW0402100RJNED" 0402 3215,4775 r90 top value=100
R169 "CRCW08058R45FKEA" 0805_HV 2970,4050 r270 bottom value=8.45
R170 "CRCW08058R45FKEA" 0805_HV 2887.76,4050 r270 bottom value=8.45
R171 "CRCW0402100RJNED" 0402 3100,4995 r270 bottom value=100
R172 "CRCW0402100RJNED" 0402 3055,4995 r270 bottom value=100
R173 "CRCW0402100RJNED" 0402 3010,4995 r270 bottom value=100
R174 "CRCW040210K0FKED" 0402 2989.8,5100 r0 bottom value=10.0k
R175 "CRCW080520R0FKEA" 0805_HV 3140,4050 r270 bottom value=20.0
R176 "CRCW080520R0FKEA" 0805_HV 3055,4050 r270 bottom value=20.0
R177 "CRCW0402100RJNED" 0402 2965,4995 r270 bottom value=100
R178 "CRCW080518R2FKEA" 0805_HV 3300,4050 r270 bottom value=18.2
R179 "CRCW06030000Z0EA" 0603 3525,3625 r90 top value=0
R180 "CRCW080518R2FKEA" 0805_HV 3220,4050 r270 bottom value=18.2
R181 "CRCW060310K0JNEA" 0603 3286.28,3520.91 r0 top value=10k
R182 "CRCW06030000Z0EA" 0603 3610,3625 r270 top value=0
R183 "CRCW0402100RJNED" 0402 2917.76,4995 r270 bottom value=100
R184 "CRCW060310K0JNEA" 0603 3697.17,3780 r270 top value=10k
R185 "CRCW0402100RJNED" 0402 2780,4995 r270 bottom value=100
R186 "CRCW0402100RFKED" 0402 2540,4206.85 r270 top value=100
R187 "CRCW040210K0FKED" 0402 2894.57,5100 r0 bottom value=10.0k
R188 "CRCW0402100RJNED" 0402 2687.76,4995 r270 bottom value=100
R189 "CRCW0402100RFKED" 0402 2540,4330 r270 top value=100
R190 "CRCW0402100RJNED" 0402 2643.15,4995 r270 bottom value=100
R191 "CRCW0402100RJNED" 0402 2735,4995 r270 bottom value=100
R192 "CRCW040210K0FKED" 0402 2625,4220 r0 top value=10.0k
R193 "CRCW040210K0FKED" 0402 2625,4356.5 r0 top value=10.0k
R194 "CRCW1206191KFKEA" 1206 2755,2675 r270 top value=191k
R195 "CRCW1206191KFKEA" 1206 2755,2865 r270 top value=191k
R196 "CRCW1206191KFKEA" 1206 2755,3055 r270 top value=191k
R197 "CRCW1206191KFKEA" 1206 2755,3245 r270 top value=191k
R198 "CRCW1206191KFKEA" 1206 2755,3435 r270 top value=191k
R199 "CRCW1206191KFKEA" 1206 2755,3625 r270 top value=191k
R200 "CRCW04023K83FKED" 0402 2625,4126.93 r0 top value=3.83k
R201 "CRCW040210R0JNED" 0402 5720,4941.89 r180 top value=10
R202 "CRCW040247K0JNED" 0402 5695.06,4995 r270 bottom value=47k
R203 "CRCW040247K0JNED" 0402 5796.23,4760 r90 top value=47k
R204 "CRCW06031K00FKEA" 0603 5094.47,3939.69 r180 top value=1.00k
R205 "CRCW0402100RJNED" 0402 5335,4995 r270 bottom value=100
R206 "CRCW060333R0JNEA" 0603 5745,4320 r270 top value=33
R207 "CRCW0402100RJNED" 0402 5380,4995 r270 bottom value=100
R208 "CRCW0402100RJNED" 0402 5650,4995 r270 bottom value=100
R209 "CRCW080510R0FKEA" 0805_HV 5220,4045 r270 bottom value=10.0
R210 "CRCW080510R0FKEA" 0805_HV 5305,4045 r270 bottom value=10.0
R211 "CRCW0402100RJNED" 0402 5745,4760 r90 top value=100
R212 "CRCW08058R45FKEA" 0805_HV 5393.5,4045 r270 bottom value=8.45
R213 "CRCW08058R45FKEA" 0805_HV 5480,4045 r270 bottom value=8.45
R214 "CRCW0402100RJNED" 0402 5605,4995 r270 bottom value=100
R215 "CRCW0402100RJNED" 0402 5560,4995 r270 bottom value=100
R216 "CRCW0402100RJNED" 0402 5515,4995 r270 bottom value=100
R217 "CRCW040210K0FKED" 0402 5503.31,5100 r0 bottom value=10.0k
R218 "CRCW080520R0FKEA" 0805_HV 5565,4045 r270 bottom value=20.0
R219 "CRCW080520R0FKEA" 0805_HV 5650,4045 r270 bottom value=20.0
R220 "CRCW0402100RJNED" 0402 5470,4995 r270 bottom value=100
R221 "CRCW080518R2FKEA" 0805_HV 5735,4045 r270 bottom value=18.2
R222 "CRCW06030000Z0EA" 0603 4715,3830 r0 top value=0
R223 "CRCW080518R2FKEA" 0805_HV 5820,4045 r270 bottom value=18.2
R224 "CRCW060310K0JNEA" 0603 5145,3520 r0 top value=10k
R225 "CRCW06030000Z0EA" 0603 4682.76,3730 r90 top value=0
R226 "CRCW0402100RJNED" 0402 5425,4995 r270 bottom value=100
R227 "CRCW060310K0JNEA" 0603 4755,3730 r90 top value=10k
R228 "CRCW0402100RJNED" 0402 5290,4995 r270 bottom value=100
R229 "CRCW0402100RFKED" 0402 5075.84,4186.16 r270 top value=100
R230 "CRCW040210K0FKED" 0402 5403.53,5100 r0 bottom value=10.0k
R231 "CRCW0402100RJNED" 0402 5200,4995 r270 bottom value=100
R232 "CRCW0402100RFKED" 0402 5075.84,4351.5 r90 top value=100
R233 "CRCW0402100RJNED" 0402 5155,4995 r270 bottom value=100
R234 "CRCW0402100RJNED" 0402 5245,4995 r270 bottom value=100
R235 "CRCW040210K0FKED" 0402 5161.5,4245 r0 top value=10.0k
R236 "CRCW040210K0FKED" 0402 5161.5,4384.06 r0 top value=10.0k
R237 "CRCW1206191KFKEA" 1206 4222.09,2355.08 r270 top value=191k
R238 "CRCW1206191KFKEA" 1206 4222.09,2560.08 r270 top value=191k
R239 "CRCW1206191KFKEA" 1206 4222.09,2765.08 r270 top value=191k
R240 "CRCW1206191KFKEA" 1206 4222.09,2970 r270 top value=191k
R241 "CRCW1206191KFKEA" 1206 4222.09,3175.08 r270 top value=191k
R242 "CRCW1206191KFKEA" 1206 4222.09,3380.08 r270 top value=191k
R243 "CRCW04023K83FKED" 0402 5161.5,4200 r0 top value=3.83k
R244 "CRCW060310R0FKEAHP" 0603 1445,1108.62 r90 top value=10.0
R245 "CRCW08054K70JNEA" 0805_HV 1669.47,580.75 r180 top value=4.7k
R246 "CRCW040266K5FKED" 0402 1854.47,160 r180 top value=66.5k
R247 "CRCW060310R0FKEAHP" 0603 2110,1108.62 r90 top value=10.0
